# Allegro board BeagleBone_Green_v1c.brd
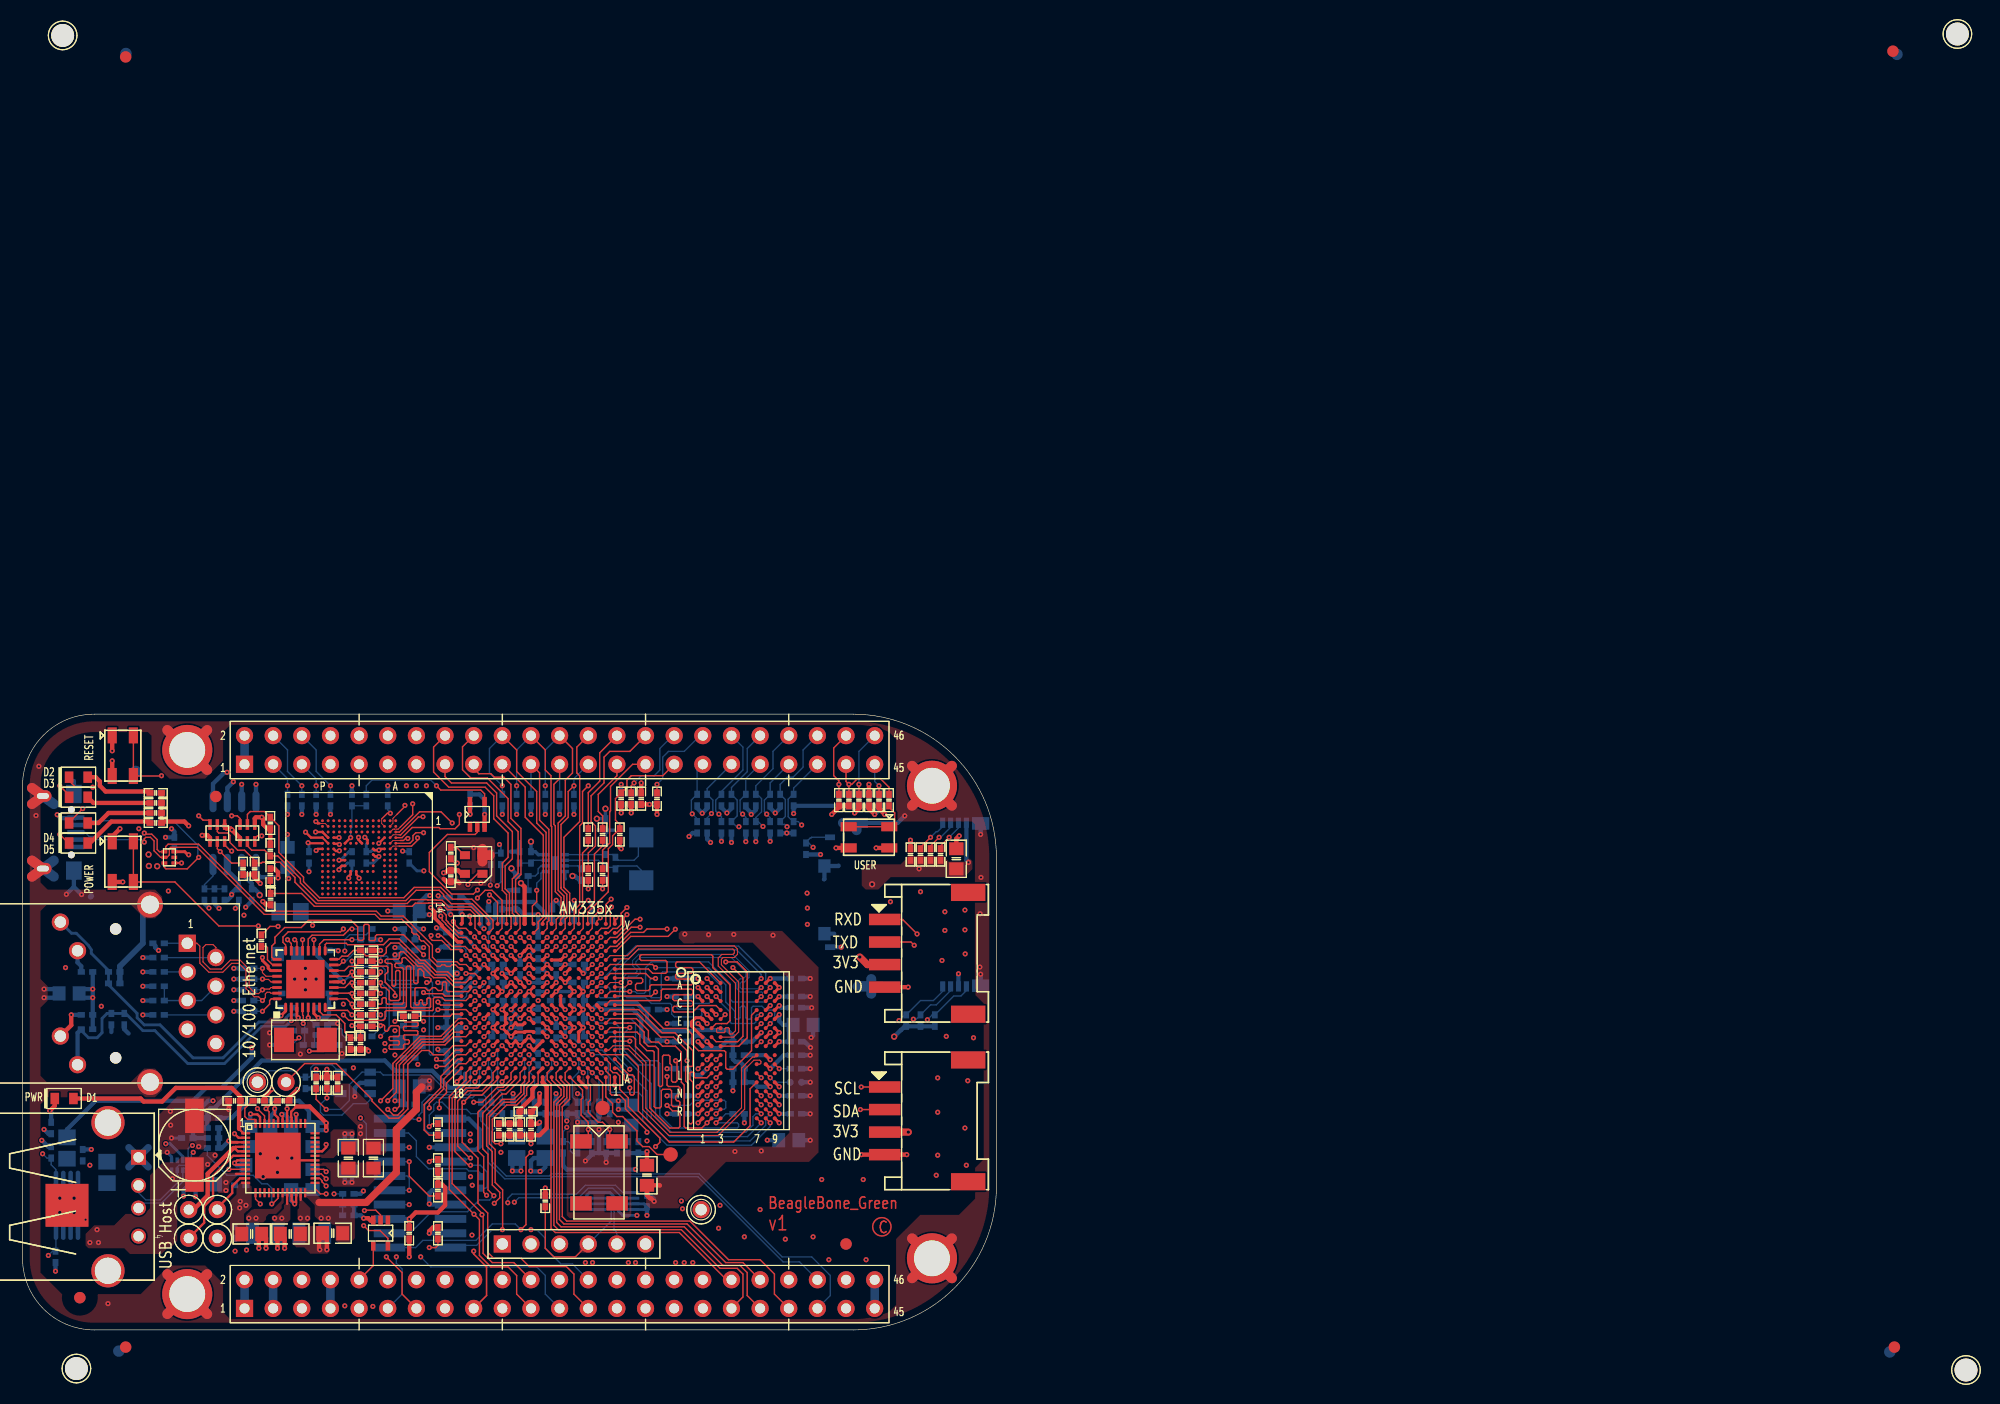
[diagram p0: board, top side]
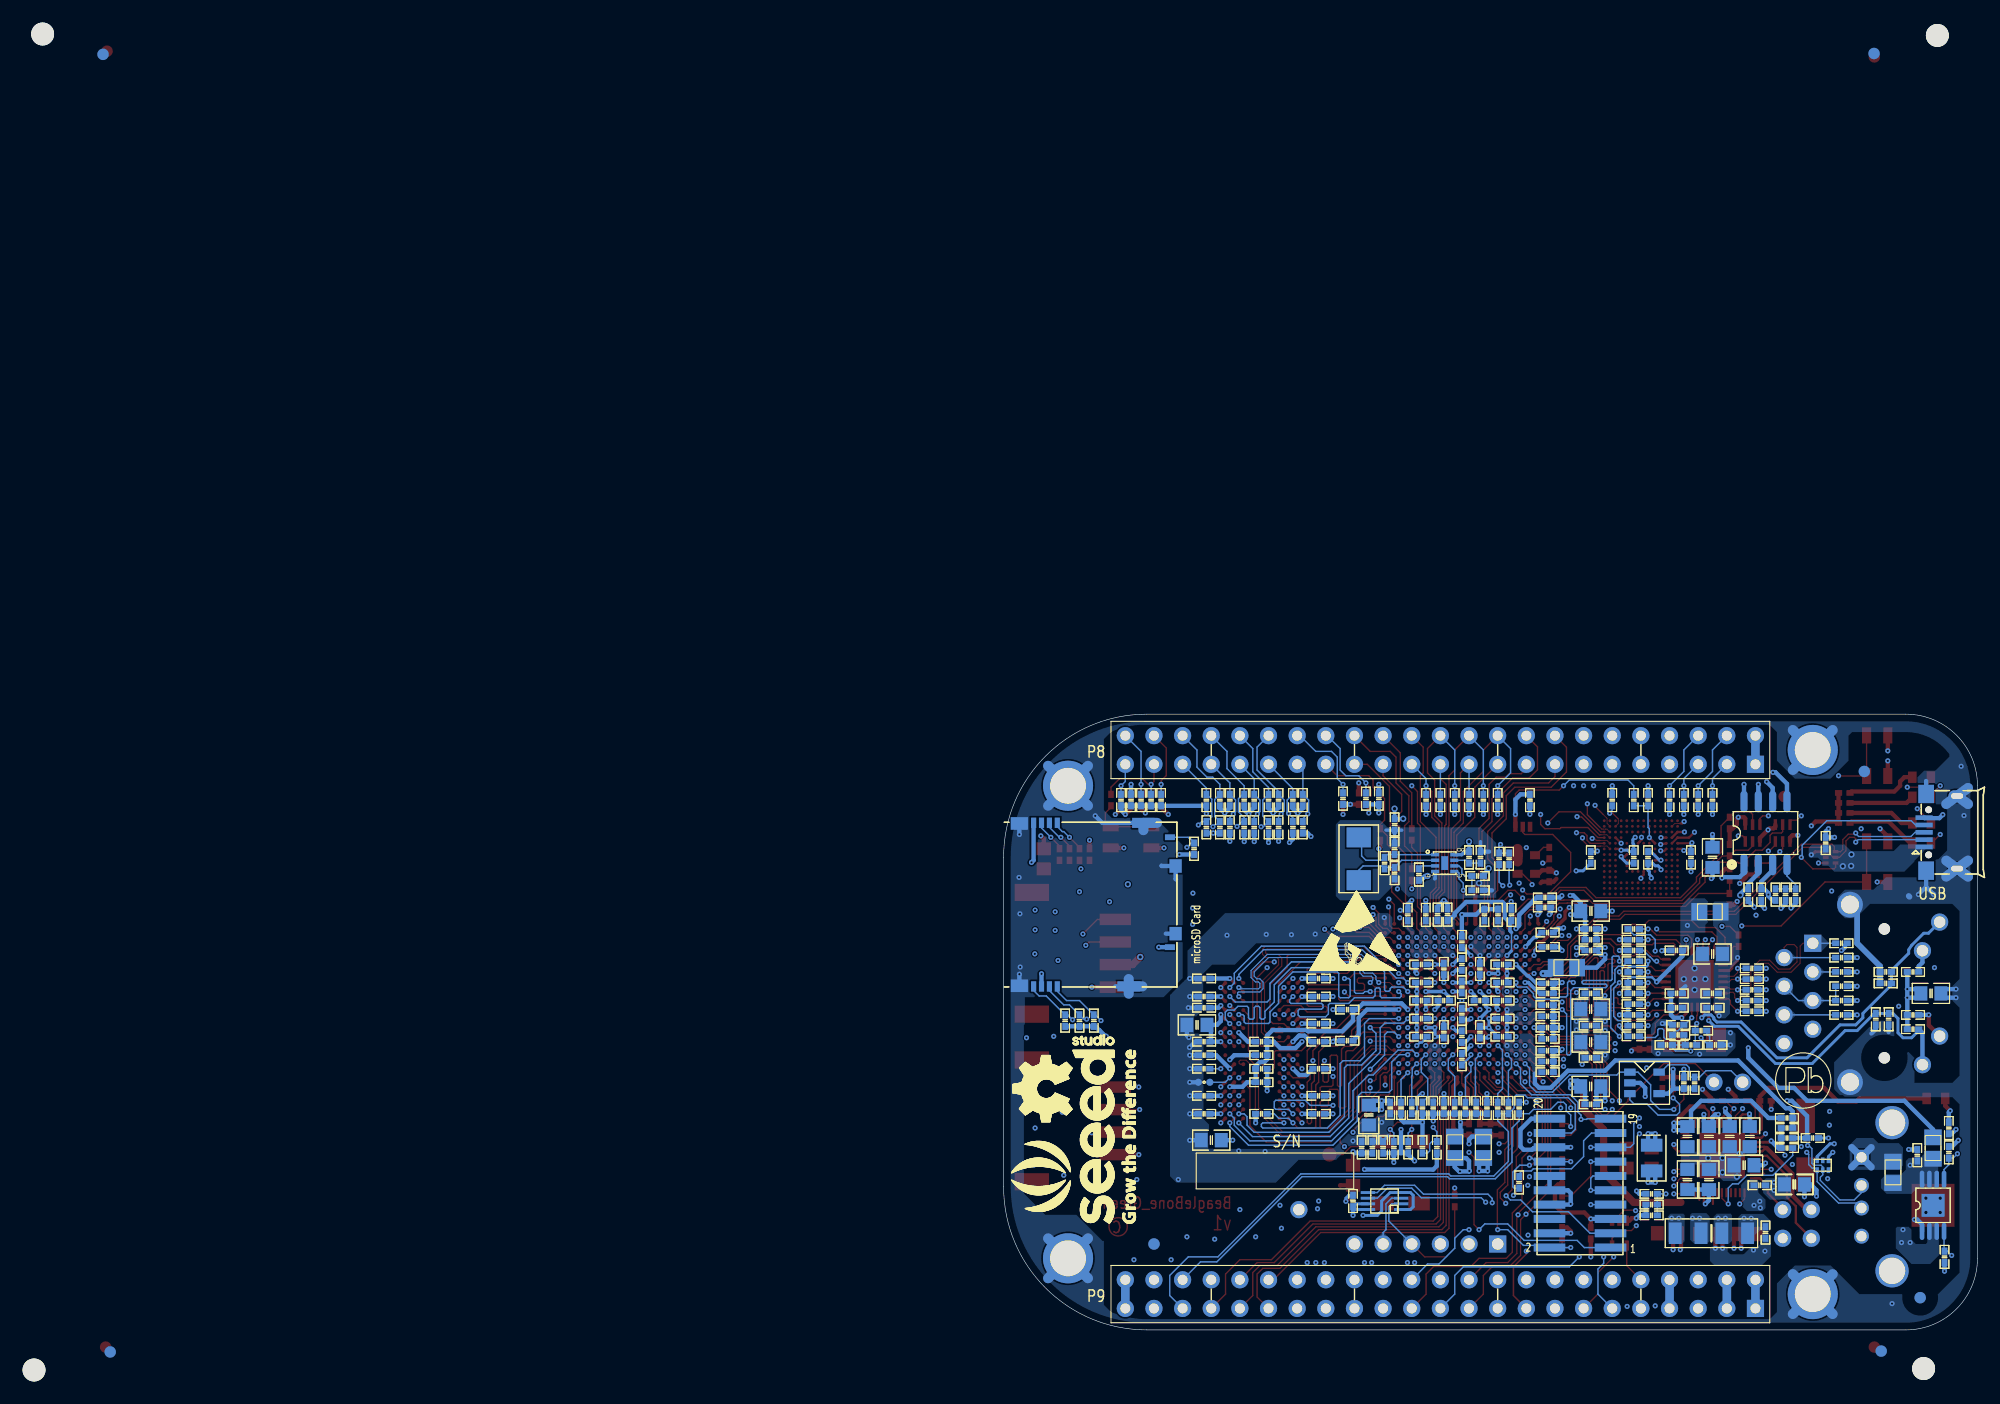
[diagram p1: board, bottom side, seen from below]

Outline 86.36 x 54.61 mm; copper layers: TOP, LYR2_GND, LYR3, LYR4, LYR5_PWR, BOTTOM. Coordinates in mm from the lower left corner of the outline.
Outline path: 0,48.26 0,6.35 arc(1.86,1.86) 6.35,0 73.66,0 arc(82.64,3.72) 86.36,12.7 86.36,41.91 arc(82.64,50.89) 73.66,54.61 6.35,54.61 arc(1.86,52.75) 0,48.26

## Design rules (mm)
constraint set DEFAULT: min track width 0.121
net group RX: nets RXN RXP
net group TX: nets TXN TXP
net group USB0: nets USB0_DM USB0_DP
net group USB1: nets USB1_DM USB1_DP
net group CLK: nets MMC0_CLKO
net group DDR_ADD: nets DDR_A0 DDR_A1 DDR_A2 DDR_A3 DDR_A4 DDR_A5 DDR_A6 DDR_A7 DDR_A8 DDR_A9 DDR_A10 DDR_A11 DDR_A12 DDR_A13 DDR_A14 DDR_BA0 DDR_BA1 DDR_BA2 DDR_CASN DDR_CKE DDR_CLK DDR_CLKN DDR_CSN DDR_ODT DDR_RASN DDR_WEN
net group DDR_DQ0: nets DDR_D0 DDR_D1 DDR_D2 DDR_D3 DDR_D4 DDR_D5 DDR_D6 DDR_D7 DDR_DQM0 DDR_DQS0 DDR_DQSN0
net group DDR_DQ1: nets DDR_D8 DDR_D9 DDR_D10 DDR_D11 DDR_D12 DDR_D13 DDR_D14 DDR_D15 DDR_DQM1 DDR_DQS1 DDR_DQSN1
nets with their own width: min track width 0.203; nets USB1_VBUS

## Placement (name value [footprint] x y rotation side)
C1  10uF,10V  [805]  20.32 8.51 180 top
C2  10uF,10V  [805]  16.23 12.9 0 bottom
C3  0.1uf,6.3V  [402]  20.95 20.32 180 top
C4  10uF,10V  [805]  20.19 17.14 90 bottom
C7  10uF,10V  [805]  23.81 13.34 270 bottom
C8  10uF,10V  [805]  25.72 13.34 270 bottom
C9  10uF,10V  [805]  23.75 8.51 180 top
C10  10uF,10V  [805]  20.7 14.61 180 bottom
C11  10uF,10V  [805]  28.89 15.24 270 top
C12  10uF,10V  [805]  27.5 8.57 0 top
C13  10uF,10V  [805]  23.81 17.14 90 bottom
C14  10uF,10V  [805]  25.72 17.14 90 bottom
C15  10uF,10V  [805]  21.97 17.14 90 bottom
C16  2.2uF,6.3V  [402]  14.61 17.02 180 bottom
C17  2.2uF,6.3V  [402]  20.32 38.61 270 bottom
C18  2.2uF,6.3V  [402]  18.8 20.32 180 top
C19  470pF,6.3V  [402]  17.02 38.61 270 bottom
C20  0.1uf,6.3V  [402]  19.18 38.61 270 bottom
C21  18pF,50V  [402]  50.48 16.19 90 bottom
C22  18pF,50V  [402]  51.75 16.19 90 bottom
C24  2.2uF,6.3V  [402]  28.89 11.11 0 bottom
C25  18pF,50V  [402]  51.69 42.67 90 bottom
C26  18pF,50V  [402]  51.69 40.51 270 bottom
C28  0.1uf,6.3V  [402]  55.88 28.41 0 bottom
C29  0.1uf,6.3V  [402]  34.29 8.57 270 top
C30  0.1uf,6.3V  [402]  28.89 10.16 0 bottom
C31  0.1uf,6.3V  [402]  43.18 17.78 270 top
C32  0.001uf,50V  [402]  42.23 17.78 270 top
C33  0.1uf,6.3V  [402]  44.13 17.78 270 top
C34  100uF,6.3V  [RD205SMD_250D]  15.24 16.38 90 top
C35  0.1uf,6.3V  [402]  5.33 15.49 90 bottom
C36  0.1uf,6.3V  [402]  13.46 43.18 90 bottom
C37  0.1uf,6.3V  [402]  27.94 21.91 270 top
C38  0.1uf,6.3V  [402]  34.29 34.61 180 bottom
C39  10uF,10V  [805]  34.29 25.53 0 bottom
C40  10uF,10V  [805]  34.29 28.45 0 bottom
C41  0.1uf,6.3V  [402]  42.12 32.41 180 bottom
C42  0.1uf,6.3V  [402]  45.72 32.41 270 bottom
C43  0.1uf,6.3V  [402]  47.32 32.01 90 bottom
C44  0.1uf,6.3V  [402]  38.12 25.81 180 bottom
C45  0.1uf,6.3V  [402]  38.1 29.84 180 bottom
C46  0.1uf,6.3V  [402]  44.12 29.21 0 bottom
C47  0.1uf,6.3V  [402]  45.72 30.41 270 bottom
C48  0.1uf,6.3V  [402]  47.32 29.21 0 bottom
C49  0.1uf,6.3V  [402]  45.72 28.01 90 bottom
C50  0.1uf,6.3V  [402]  47.32 26.41 90 bottom
C51  0.1uf,6.3V  [402]  34.29 29.84 180 bottom
C52  0.1uf,6.3V  [402]  34.29 26.99 180 bottom
C53  0.1uf,6.3V  [402]  34.29 24.13 180 bottom
C54  0.1uf,6.3V  [402]  38.12 26.81 180 bottom
C55  10uF,10V  [805]  31.11 15.24 270 top
C56  0.1uf,6.3V  [402]  45.72 34.41 270 bottom
C57  0.1uf,6.3V  [402]  54.86 47.12 270 top
C58  0.1uf,6.3V  [402]  42.52 36.81 90 bottom
C59  0.1uf,6.3V  [402]  43.5 19.68 270 bottom
C60  0.1uf,6.3V  [402]  42.12 27.61 180 bottom
C61  0.1uf,6.3V  [402]  75.06 46.99 270 top
C62  10uF,10V  [805]  34.29 21.59 0 bottom
C63  0.1uf,6.3V  [402]  44.12 26.41 90 bottom
C64  0.1uf,6.3V  [402]  34.29 20 180 bottom
C65  0.1uf,6.3V  [402]  42.12 29.21 180 bottom
C66  0.1uf,6.3V  [402]  42.12 30.81 180 bottom
C67  0.1uf,6.3V  [402]  34.29 35.56 180 bottom
C68  0.1uf,6.3V  [402]  48.92 36.81 270 bottom
C69  0.1uf,6.3V  [402]  38.12 28.81 0 bottom
C70  0.1uf,6.3V  [402]  42.12 26.01 180 bottom
C71  0.1uf,6.3V  [402]  38.35 37.47 180 bottom
C72  0.1uf,6.3V  [402]  45.72 26.01 270 bottom
C73  0.1uf,6.3V  [402]  49.32 32.41 0 bottom
C74  0.1uf,6.3V  [402]  50.52 36.81 270 bottom
C75  0.1uf,6.3V  [402]  53.09 47.12 270 bottom
C76  0.1uf,6.3V  [402]  75.06 46.99 270 bottom
C77  10uF,10V  [805]  34.29 37.15 180 bottom
C78  0.1uf,6.3V  [402]  34.29 33.66 0 bottom
C79  0.1uf,6.3V  [402]  38.12 27.81 180 bottom
C80  0.1uf,6.3V  [402]  41.32 36.81 90 bottom
C81  0.1uf,6.3V  [402]  47.88 36.83 90 bottom
C82  0.1uf,6.3V  [402]  38.12 24.77 180 bottom
C83  0.1uf,6.3V  [402]  38.12 23.81 180 bottom
C84  0.1uf,6.3V  [402]  46.99 36.83 90 bottom
C85  0.1uf,6.3V  [402]  38.12 22.86 180 bottom
C86  0.1uf,6.3V  [402]  38.12 35.24 180 bottom
C87  0.1uf,6.3V  [402]  38.1 30.73 180 bottom
C88  0.1uf,6.3V  [402]  45.72 24.01 270 bottom
C89  1uF,10V  [402]  46.35 19.68 270 bottom
C90  1uF,10V  [402]  44.45 19.68 270 bottom
C91  1uF,10V  [402]  45.4 19.68 270 bottom
C92  0.1uf,6.3V  [402]  48.26 19.68 270 bottom
C93  0.1uf,6.3V  [402]  45.09 17.78 270 top
C94  0.1uf,6.3V  [402]  44.12 32.01 270 bottom
C95  10uF,10V  [805]  53.98 19.05 90 bottom
C96  10uF,10V  [805]  55.37 13.72 90 top
C97  0.1uf,6.3V  [402]  49.32 30.81 180 bottom
C98  0.1uf,6.3V  [402]  49.32 29.21 180 bottom
C99  0.1uf,6.3V  [402]  49.32 27.61 180 bottom
C100  0.1uf,6.3V  [402]  49.32 26.01 180 bottom
C101  0.1uf,6.3V  [402]  52.07 19.68 270 bottom
C102  0.1uf,6.3V  [402]  53.66 16.19 90 bottom
C103  0.1uf,6.3V  [402]  54.61 16.19 90 bottom
C104  1uF,10V  [402]  49.21 19.68 270 bottom
C105  0.1uf,6.3V  [402]  47.31 19.68 270 bottom
C106  1uF,10V  [402]  43.72 36.81 90 bottom
C107  0.1uf,6.3V  [402]  58.42 31.17 180 bottom
C108  0.1uf,6.3V  [402]  58.42 29.57 180 bottom
C109  0.1uf,6.3V  [402]  58.42 27.17 180 bottom
C110  0.1uf,6.3V  [402]  58.42 25.57 180 bottom
C111  0.1uf,6.3V  [402]  58.42 23.16 180 bottom
C112  0.1uf,6.3V  [402]  58.42 20.76 180 bottom
C113  0.1uf,6.3V  [402]  58.42 19.16 180 bottom
C114  0.1uf,6.3V  [402]  68.58 31.17 0 bottom
C115  0.1uf,6.3V  [402]  68.58 29.57 0 bottom
C116  0.1uf,6.3V  [402]  68.58 28.57 0 bottom
C117  0.1uf,6.3V  [402]  68.58 25.57 0 bottom
C118  10uF,10V  [805]  69.22 27.05 180 bottom
C119  0.1uf,6.3V  [402]  68.58 24.36 0 bottom
C120  0.1uf,6.3V  [402]  68.58 20.76 0 bottom
C121  0.1uf,6.3V  [402]  68.58 19.16 0 bottom
C122  10uF,10V  [805]  67.94 16.83 180 bottom
C123  0.001uf,50V  [402]  63.5 24.36 0 bottom
C124  0.1uf,6.3V  [402]  63.5 21.96 180 bottom
C125  2.2uF,6.3V  [402]  32.38 46.99 90 bottom
C126  10uF,10V  [805]  23.5 41.91 90 bottom
C127  0.1uf,6.3V  [402]  25.4 41.91 270 bottom
C128  0.1uf,6.3V  [402]  29.21 41.91 90 bottom
C129  0.1uf,6.3V  [402]  30.48 41.91 270 bottom
C130  0.1uf,6.3V  [402]  34.29 41.91 270 bottom
C131  0.1uf,6.3V  [402]  23.5 28.57 0 bottom
C132  0.1uf,6.3V  [402]  23.5 29.84 0 bottom
C133  10uF,10V  [805]  23.5 33.34 180 bottom
C134  1uF,10V  [402]  26.67 28.57 180 bottom
C135  0.1uf,6.3V  [402]  26.67 33.66 0 bottom
C136  470pF,6.3V  [0402]  26.67 29.84 180 bottom
C137  33pF,4 EMI  [402]  12.06 34.29 180 bottom
C138  33pF,4 EMI  [402]  12.06 33.02 180 bottom
C139  33pF,4 EMI  [402]  12.06 31.75 180 bottom
C140  33pF,4 EMI  [402]  12.06 27.94 180 bottom
C141  0.022uF,10V  [402]  12.06 30.48 180 bottom
C142  30pF,50V  [402]  23.24 25.27 180 bottom
C143  30pF,50V  [402]  27.56 25.27 0 bottom
C152  0.1uf,6.3V  [402]  26.04 21.91 90 bottom
C153  10uF,10V  [805]  82.8 41.78 90 top
C154  0.1uf,6.3V  [402]  78.74 42.16 90 top
C155  0.1uf,6.3V  [402]  55.37 11.43 270 bottom
C158  0.1uf,6.3V  [402]  39.69 46.99 90 bottom
C159  0.1uf,6.3V  [402]  37.97 40.26 270 top
C161  33pF,4 EMI  [402]  26.54 27.05 0 bottom
C162  33pF,4 EMI  [402]  29.08 25.4 90 top
C163  100pF,4 EMI  [402]  8.13 31.75 0 bottom
C164  100pF,4 EMI  [402]  9.02 27.56 270 bottom
C165  100nF,4 EMI  [402]  8.13 30.73 0 bottom
C166  100nF,4 EMI  [402]  7.87 27.56 270 bottom
D1  LTST-C191TBKT  [LED_0603]  3.68 20.52 0 top
D2  LTST-C191TBKT  [LED_0603]  4.95 49.02 0 top
D3  LTST-C191TBKT  [LED_0603]  4.95 47.24 0 top
D4  LTST-C191TBKT  [LED_0603]  4.95 44.96 0 top
D5  LTST-C191TBKT  [LED_0603]  4.95 43.18 0 top
FB1  150OHM800mA  [SM-7351-IND-0805]  36.45 32.13 0 bottom
FB2  150OHM800mA  [SM-7351-IND-0805]  46.35 16.19 270 bottom
FB3  150OHM800mA  [SM-7351-IND-0805]  43.81 16.19 270 bottom
FB4  150OHM800mA  [SM-7351-IND-0805]  23.72 37.08 180 bottom
FB7  150OHM800mA  [SM-7351-IND-0805]  7.49 13.97 90 bottom
FB8  0.1R,0805  [SM-7351-IND-0805]  3.94 16.13 270 bottom
J1  HEADER 6  [SIP6]  42.55 7.62 90 top
J4  GroveHDR  [4P-SMD-2_0-90D]  76.45 18.54 270 top
J5  GroveHDR  [4P-SMD-2_0-90D]  76.45 33.4 270 top
L1  LQM2HPN2R2MG0L  [2520]  21.53 8.57 180 bottom
L2  LQM2HPN2R2MG0L  [2520]  25.65 8.57 0 bottom
L3  LQM2HPN2R2MG0L  [2520]  28.89 15.24 270 bottom
MTG1  MHOLE  [MTGH200C125D_PL]  14.61 3.17 90 top
MTG2  MHOLE  [MTGH200C125D_PL]  80.64 6.35 90 top
MTG3  MHOLE  [MTGH200C125D_PL]  14.61 51.44 90 top
MTG4  MHOLE  [MTGH200C125D_PL]  80.64 48.26 90 top
NOREF  -  []  86.36 27.94 0 top
NOREF#2  -  []  85.72 28.57 0 top
NOREF#3  -  [unnamed#2]  5.08 2.86 270 top
NOREF#4  -  []  6.35 54.61 0 top
NOREF#5  -  []  81.92 52.07 0 top
NOREF#6  -  []  80.64 6.35 0 top
NOREF#7  -  []  86.36 12.7 0 top
NOREF#8  -  []  0 0 0 top
NOREF#9  -  [unnamed#2]  17.14 47.31 270 top
NOREF#10  -  []  85.72 28.57 0 top
NOREF#11  -  []  -368.3 -256.54 0 top
NOREF#12  -  []  14.61 3.17 0 top
NOREF#13  -  [unnamed#3]  172.34 -3.56 0 top
NOREF#14  -  []  86.36 39.69 0 top
NOREF#15  -  [unnamed#2]  73.03 7.62 270 top
NOREF#16  -  [unnamed#3]  171.58 114.94 180 top
NOREF#17  -  []  80.64 48.26 0 top
NOREF#18  -  []  0 0 0 top
NOREF#19  -  []  85.72 39.05 0 top
NOREF#20  -  [unnamed#3]  3.56 114.81 180 top
NOREF#21  -  []  14.61 51.44 0 top
NOREF#22  -  [unnamed#2]  165.99 -1.52 270 top
NOREF#23  -  [unnamed#2]  9.14 112.9 270 top
NOREF#24  -  []  -368.17 -256.47 0 top
NOREF#25  -  [unnamed#3]  4.78 -3.43 0 top
NOREF#26  -  []  14.61 3.17 0 top
NOREF#27  -  [unnamed#2]  9.14 -1.52 270 top
NOREF#28  -  []  80.64 6.35 0 top
NOREF#29  -  [unnamed#2]  165.86 113.41 270 top
NOREF#30  -  []  -11.96 0 90 top
NOREF#31  -  []  0 -11.96 0 top
NOREF#32  -  [unnamed#2]  5.08 2.86 270 bottom
NOREF#33  -  [unnamed#2]  8.53 -1.88 270 bottom
NOREF#34  -  []  83.82 13.97 90 bottom
NOREF#35  -  [unnamed#2]  165.58 -1.96 270 bottom
NOREF#36  -  [unnamed#2]  166.22 113.13 90 bottom
NOREF#37  -  [unnamed#2]  10.03 49.53 270 bottom
NOREF#38  -  []  1.91 53.34 180 bottom
NOREF#39  -  [unnamed#2]  73.03 7.62 270 bottom
NOREF#40  -  [unnamed#2]  9.17 113.21 90 bottom
P2  CTI JTAG,DNI  [HEADER10X2_SMD]  35.24 13.02 90 bottom
P3  DIP USB A TYPE FMAL  [USB-003A-4P-90D]  7.57 11.81 270 top
P4  SMD Micro USB-B-without POST-W/P  [5P-USB-B]  4.98 44.13 90 bottom
P5  LPJ0011BBNL  [RJ45-7499010211A]  14.61 34.29 270 top
P8  FEMALE HEADER 2x23  [HEADER23X2]  19.68 50.16 0 top
P9  FEMALE HEADER 2x23  [HEADER23X2]  19.68 1.91 0 top
P10  SCHA5B0200  [SD-MICRO-SCHA5B0300]  81.6 37.72 270 bottom
Q1  DMC56404  [SMINI6-F3-B]  19.94 44.07 180 top
Q2  DMC56404  [SMINI6-F3-B]  17.27 44.07 180 top
R1  100K,1%  [402]  23.11 20.32 180 top
R3  1.5K,1%  [402]  26.04 21.91 270 top
R4  1.5K,1%  [402]  26.99 21.91 270 top
R5  0,1%  [402]  16.89 17.02 180 bottom
R6  0,1%  [402]  18.8 8.64 270 bottom
R7  0,1%  [402]  16.89 16.13 180 bottom
R8  0,1%  [402]  16.89 17.91 180 bottom
R9  0,1%,DNI  [402]  16.89 18.8 0 bottom
R10  470K,1%  [402]  16.13 38.61 270 bottom
R11  280K,1%  [402]  17.91 38.61 90 bottom
R12  4.75K,5%  [402]  2.54 17.91 90 bottom
R14  10K,1%  [402]  28.89 12.06 180 bottom
R17  1M,1%  [402]  52.58 41.4 270 bottom
R18  33  [0402]  40.64 13.08 90 bottom
R19  0,1%  [402]  41.59 19.68 270 bottom
R20  0,1%  [402]  42.55 19.68 90 bottom
R22  49.9,1%  [402]  55.88 25.65 180 bottom
R23  4.75K,1%  [402]  36.83 12.38 270 top
R24  4.75K,1%  [402]  36.83 14.61 90 top
R25  4.75K,1%  [402]  36.83 8.57 90 top
R26  4.75K,1%  [402]  50.16 19.68 90 bottom
R27  0,1%  [402]  44.61 19.37 180 top
R28  33  [0402]  34.29 27.81 180 top
R29  0,1%  [402]  51.69 44.83 270 bottom
R30  0,1%  [402]  52.7 16.19 270 bottom
R45  22  [0402]  50.16 43.94 90 top
R46  0  [0402]  51.44 43.94 90 top
R47  0  [0402]  51.44 40.39 90 top
R48  0  [0402]  50.16 40.39 90 top
R49  0,1%  [402]  38.1 33.97 0 bottom
R50  0,1%  [402]  36.83 17.78 270 top
R51  0,1%  [402]  40.64 19.68 90 bottom
R52  10K,1%  [402]  2.54 15.75 270 bottom
R53  10K,1%  [402]  2.92 6.48 270 bottom
R54  10K,1%  [402]  51.12 19.68 90 bottom
R55  100K,1%,DNI  [402]  54.23 47.12 90 bottom
R56  100K,1%  [402]  53.09 47.12 90 top
R57  100K,1%,DNI  [402]  59.82 46.99 90 bottom
R58  100K,1%,DNI  [402]  60.71 46.99 90 bottom
R59  100K,1%,DNI  [402]  56.26 47.12 90 bottom
R60  100K,1%,DNI  [402]  61.98 46.99 90 bottom
R61  100K,1%,DNI  [402]  62.87 46.99 90 bottom
R62  100K,1%,DNI  [402]  64.14 46.99 90 bottom
R63  100K,1%,DNI  [402]  65.02 46.99 90 bottom
R64  100K,1%,DNI  [402]  66.29 46.99 90 bottom
R65  100K,1%  [402]  67.18 46.99 90 bottom
R66  100K,1%  [402]  68.38 46.99 90 bottom
R67  100K,1%  [402]  72.39 46.99 90 bottom
R68  100K,1%  [402]  73.28 46.99 90 bottom
R69  100K,1%,DNI  [402]  74.17 46.99 90 bottom
R70  100K,1%,DNI  [402]  75.95 46.99 90 bottom
R71  4.75K,5%  [402]  11.81 44.96 180 top
R72  4.75K,5%  [402]  11.81 47.62 180 top
R73  4.75K,5%  [402]  11.81 46.74 180 top
R74  4.75K,5%  [402]  11.81 45.85 180 top
R75  100,1%  [402]  76.83 46.99 270 top
R76  100K,1%  [402]  21.97 42.55 90 top
R77  100K,1%  [402]  21.97 44.96 270 top
R78  100K,1%  [402]  19.56 40.89 270 top
R79  100K,1%  [402]  20.57 40.89 270 top
R80  100K,1%  [402]  53.98 47.12 270 top
R81  100K,1%,DNI  [402]  52.96 43.94 270 top
R82  100K,1%  [402]  59.82 44.58 270 bottom
R83  100K,1%  [402]  60.71 44.58 270 bottom
R84  100K,1%  [402]  56.26 47.12 270 top
R85  100K,1%  [402]  61.98 44.58 270 bottom
R86  100K,1%  [402]  62.87 44.58 270 bottom
R87  100K,1%  [402]  64.14 44.58 270 bottom
R88  100K,1%  [402]  65.02 44.58 270 bottom
R89  100K,1%  [402]  66.29 44.58 270 bottom
R90  100K,1%,DNI  [402]  67.18 44.58 270 bottom
R91  100K,1%,DNI  [402]  68.38 44.58 270 bottom
R92  100K,1%,DNI  [402]  72.39 46.99 270 top
R93  100K,1%,DNI  [402]  73.28 46.99 270 top
R94  100K,1%  [402]  74.17 46.99 270 top
R95  100K,1%  [402]  75.95 46.99 270 top
R96  10K,1%  [402]  68.58 23.16 180 bottom
R97  1.5K,1%  [402]  63.5 19.16 180 bottom
R98  10K,1%  [402]  63.5 25.57 180 bottom
R99  240  [SM-7351-RES-0402]  68.58 21.96 180 bottom
R100  10K,1%  [402]  63.5 23.16 180 bottom
R101  10K,1%  [402]  48.9 46.99 90 bottom
R102  10K,1%  [402]  46.35 46.99 90 bottom
R103  10K,1%  [402]  26.04 46.99 90 bottom
R104  10K,1%  [402]  27.3 46.99 90 bottom
R105  10K,1%  [402]  47.62 46.99 90 bottom
R106  10K,1%  [402]  43.81 46.99 90 bottom
R107  10K,1%  [402]  23.5 46.99 90 bottom
R108  10K,1%  [402]  24.77 46.99 90 bottom
R109  10K,1%  [402]  42.55 46.99 90 bottom
R110  10K,1%  [402]  45.09 46.99 90 bottom
R111  10K,1%  [402]  29.21 46.99 270 bottom
R112  1.5K,1%  [402]  30.48 30.8 0 bottom
R113  1.5K,1%  [402]  30.48 33.66 0 bottom
R114  1.5K,1%  [402]  30.48 29.84 0 bottom
R115  10K,1%  [402]  30.48 31.75 0 bottom
R116  10K,1%  [402]  30.48 27.94 0 bottom
R117  10K,1%  [402]  30.48 28.89 0 bottom
R118  10K,1%  [402]  29.97 25.4 270 top
R119  1.5K,1%  [402]  30.48 33.66 180 top
R120  49.9,1%  [402]  20 29.21 180 bottom
R121  49.9,1%  [402]  20 30.16 180 bottom
R122  49.9,1%  [402]  20 31.11 180 bottom
R123  49.9,1%  [402]  20 32.07 180 bottom
R124  10,1%,DNI  [402]  30.48 26.92 180 top
R125  100,1%  [402]  30.48 27.94 180 top
R126  100,1%  [402]  30.48 28.89 180 top
R127  100,1%  [402]  30.48 29.84 180 top
R128  100,1%  [402]  30.48 30.8 180 top
R129  100,1%  [402]  21.18 34.52 270 top
R130  470,5%  [402]  5.71 27.94 180 bottom
R131  100,1%  [402]  30.48 26.99 180 bottom
R132  470,5%  [402]  5.71 31.75 180 bottom
R133  100,1%  [402]  30.48 31.75 180 top
R134  100,1%  [402]  30.48 35.56 180 bottom
R135  10K,1%  [402]  5.71 26.67 0 bottom
R136  0.1R,0805  [805]  4.13 29.84 180 bottom
R137  0,1%  [402]  12.06 29.21 180 bottom
R138  100,1%  [402]  30.48 32.7 180 bottom
R139  100,1%  [402]  30.48 32.7 180 top
R140  0,1%,DNI  [402]  30.48 26.04 180 bottom
R141  1M,1%,DNI  [402]  25.4 25.27 0 bottom
R142  0,1%  [402]  26.54 26.16 0 bottom
R143  10,1%  [402]  24.51 26.54 180 bottom
R144  12.1K,1%  [402]  20 28.26 180 bottom
R145  10K,1%  [402]  30.48 34.61 0 bottom
R150  10K,1%  [402]  79.63 42.16 90 top
R151  10K,1%  [402]  81.41 42.16 90 top
R152  10K,1%  [402]  80.9 27.43 90 bottom
R153  10K,1%  [402]  79.63 27.43 90 bottom
R154  10K,1%  [402]  78.36 27.43 90 bottom
R155  10K,1%  [402]  80.52 42.16 90 top
R156  10K,1%  [402]  25.08 21.91 90 bottom
R157  10K,1%  [402]  69.47 42.67 270 bottom
R159  0,1%  [402]  38.35 38.35 0 bottom
R160  0,1%  [402]  42.42 41.78 90 bottom
R161  0,1%  [402]  41.53 41.78 90 bottom
R162  0,1%  [402]  30.48 46.99 270 bottom
R163  4.75K,1%  [402]  47.94 16.19 90 bottom
R164  4.75K,1%  [402]  49.21 16.19 90 bottom
R165  100K,1%  [402]  46.35 11.43 90 top
R167  33  [0402]  37.97 42.29 270 top
R168  0R,1%  [402]  19.3 12.83 180 bottom
R169  0,1% DNP  [402]  21.97 40.39 90 top
R170  0,1% DNP  [402]  22 38.2 270 top
R171  4.75K,5%  [402]  49.53 40.39 90 bottom
R172  4.75K,5%  [402]  44.32 40.26 0 bottom
R173  4.75K,5%  [402]  44.07 41.91 90 bottom
R174  4.75K,5%,DNP  [402]  44.32 38.99 180 bottom
R175  4.75K,5%.DNP  [402]  45.09 41.91 270 bottom
S1  SMD Button Top  [SW_4P]  8.89 50.93 270 top
S2  SMD Button Top  [SW_4P]  75.06 43.69 180 top
S3  SMD Button Top  [SW_4P]  8.89 41.53 270 top
TP1  TESTPT1  [TP1-8040]  60.17 10.67 0 top
TP2  TESTPT1  [TP60C_SMD]  57.47 15.56 0 top
TP3  TESTPT1  [TP60C_SMD]  51.44 19.68 0 top
TP4  TESTPT1  [TP1-8040]  20.83 21.97 0 top
TP5  TESTPT1  [TP60C33D]  14.73 10.67 0 top
TP6  TESTPT1  [TP60C33D]  14.73 8.13 0 top
TP7  TESTPT1  [TP60C33D]  17.27 10.67 0 top
TP8  TESTPT1  [TP60C33D]  17.27 8.13 0 top
TP9  TESTPT1  [TP60C33D]  23.37 21.97 0 top
U2  TPS65217C  [U_48_RSL]  22.86 15.24 0 top
U3  SN74LVC1G06DCK  [DCK5_2P15X1P4]  40.32 45.72 0 top
U4  TL5209  [SO8-25X75]  18.8 44.07 180 bottom
U5  AM3358BZCZ100  [AM33XX_15X15]  45.72 29.21 180 top
U7  24LC32A  [SOT23-5]  29.53 21.91 270 bottom
U8  TPS2051 (DGN)  [DGN-16X60]  3.94 11.05 180 bottom
U9  TPD4S012  [U_6_DRY]  13.72 14.61 180 bottom
U10  TPD4S012  [U_6_DRY]  13.02 41.91 270 top
U12  MT41K256M16HA -125:E  [BGA96_T9_P8_9X14]  63.5 24.77 0 top
U13  MEM_MNAND_4GB  [BGA153_P14_P5_11P5X13]  29.84 41.91 270 top
U14  LAN8710A  [QFN32_5X5MM_EP3P3MM]  25.08 31.11 0 top
U15  SN74LVC2G241  [U_8_DCU]  52.58 11.43 90 bottom
U16  SN74LVC1G07DCK  [DCK5_2P15X1P4]  31.75 8.59 180 top
U17  SSDCI3128AF  [TDFN8_P5_2P0]  47.24 41.4 270 bottom
Y1  32.768KHz MC-306  [XTAL4_126-216SMD]  51.12 13.97 270 top
Y2  24MHz  [XTAL150SMD_125X196]  54.86 41.78 90 bottom
Y3  25.000MHz  [XTAL150SMD_125X196]  25.08 25.72 180 top
Y4  24.576MHZ  [OSC4_61X65LS_79X98SMD]  40.01 41.27 90 top

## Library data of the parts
C1 C2 C4 C7-C15 C39 C40 C55 C62 C77 C95 C96 C118 C122 C126 C133 C153 = CAP_10uF_Y5V_10V_10%_0805
C3 C20 C28-C31 C33 C35-C38 C41-C54 C56-C61 C63-C76 C78-C88 C92-C94 C97-C103 C105 C107-C117 C119-C121 C124 C127-C132 C135 C152 C154 C155 C158 C159 = CAP_0.1uF_X5R_6.3V_20% 0201
C16-C18 C125 = CAP_2.2uF_X5R_6.3V_10%_0402
C19 = CAP_470PF_X7R_25V_10%_0402
C21 C22 C25 C26 = CAP_18PF_COG_50V_5%_0402
C24 C89-C91 C104 C106 C134 = CAP_1.0UF_X5R_10V_10%_0402
C32 C123 = CAP_0.001_X7R_50V_5%_0402
C34 = CAP_100UF_TANT_6.3V_3528-21
C136 = 470pF/5%/50V/C0G/0603_0
C137-C140 C161-C166 = CAP_0402_100pF_COG_50V
C141 = CAP_0402_0.1uf_X5R_10V
C142 C143 = CAP_30PF_COG_50V_5%_0402
D1-D5 = LED_LTST-C150GKT_0
FB1-FB4 FB7 FB8 = FER_180_200_0
J1 = HEADER 6: User Part Number: ***
J4 J5 = HEADER 4
L1-L3 = IND_2.2uH_2.6A_10%_SMD
MTG1-MTG4 = MHOLE
P2 = HDR_10x2_CJTAG_0
P3 = CONN_54819-0578_2
P4 = MINI-USB-AB-SOCKET
P5 = CONN_RJ45_MAG_WE_0
P8 P9 = HDR_46_F_2_0.1_0.1
P10 = microSD_CONN_8: User Part Number: X; Tolerance: X
Q1 Q2 = RN1907
R1 R55-R70 R75-R95 R165 = RES_100K_1/16W_1%_0402
R3 R4 R119 R168 = RES_1.5K_1/16W_5%_0402
R5-R9 R23-R26 R50 R51 R112-R118 R159-R164 R169 R170 = RES_4.75K_1/16W_1%_0402
R10 R12 R71-R74 R130 R132 R171-R175 = RES_470_1/10W_5%_0402
R11 = RES_470_1/10W_5%_0402: signal model: 33OHMRESISTOR1_16W5_0402_SM_735_33
R14 = RES_10K_1/16W_1%_0402: signal model: 33OHMRESISTOR1_16W5_0402_SM_735_33
R17 = RES_1M_1/16W_1%_0402: signal model: 33OHMRESISTOR1_16W5_0402_SM_735_33
R18 R47 = RES_33_0402: signal model: 33OHMRESISTOR1_16W5_0402_SM_735_33
R19 R27 R29 R30 R140 R142 R156 = RES_0_1/16W_1%_0402
R20 = RES_0_1/16W_1%_0402: signal model: 33OHMRESISTOR1_16W5_0402_SM_735_33
R22 R120-R123 = RES_4.7K_0402
R28 R45 R46 R48 R167 = RES_33_0402
R49 = RES_100K_1/16W_1%_0402: signal model: 33OHMRESISTOR1_16W5_0402_SM_735_33
R52-R54 R96-R98 R100-R111 R135 R137 R143 R145 R150-R155 R157 = RES_10K_1/16W_1%_0402
R99 = Res
R124-R126 R129 R134 R138 = 100-1/10W-1%-0603_4
R127 R128 R131 R133 R139 = RES_100_1/10W_5%_0402
R136 = RES_0.1_0805
R141 = RES_1M_1/16W_1%_0402
R144 = RES_12.1K_1/16W_1%_0402
S1 S3 = SW_KT11P2JM_2
S2 = SW_KT11P2JM_1
TP1-TP9 = TESTPT1
U2 = PWR_TPS65217_2
U3 = IC_SN74LVC1G06DCK_0
U4 = PWR_TLV70233DBV_0: Tolerance: X; User Part Number: X
U5 = IC_AM335X_ZCZ
U7 = MEM_24LC32_SOT23-5
U8 = TPS2061_1: User Part Number: X; Tolerance: X
U9 U10 = PROT_TPD4S012
U12 = MT47H256M8_7
U13 = MEM_MNAND_2GB
U14 = LAN8710 QFN32_1
U15 = IC_SN74LVC2G241_1
U16 = IC_SN74LVC1G07DCK
U17 = SSDCI3128AF
Y1 = CRYS_32_768KHz_SMD32_1
Y2 = CRYS_24MHz_SCC_0
Y3 = Suntsu ITEMP 25MHz _0.005% 20pf
Y4 = OSC_12MHz_1.3V: Tolerance: TOL*; User Part Number: P/N*

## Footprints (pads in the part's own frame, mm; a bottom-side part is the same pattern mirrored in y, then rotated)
4P-SMD-2_0-90D
  rect 1.524x3.048 smd: (-5.4,7.4) (5.4,7.4)
  rect 1.016x2.794 smd: 1(-3,0) 2(-1,0) 3(1,0) 4(3,0)
5P-USB-B
  round 0.61 hole 0.61 unplated: (-2,-0.65) (2,-0.65)
  rect 0.406x1.524 smd: 1(-1.3,-0.25) 2(-0.65,-0.25) 3(0,-0.25) 4(0.65,-0.25) 5(1.3,-0.25)
  rect 1.626x1.397 smd: 6(3.4,-0.427) 7(-3.4,-0.427)
  oval 1.016x1.524 hole 0.508x1.067: 8(-3.22,-3.175) 9(3.22,-3.175)
402
  rect 0.635x0.508 smd: 1(-0.508,0) 2(0.508,0)
0402
  rect 0.635x0.508 smd: 1(-0.508,0) 2(0.508,0)
805
  rect 1.143x1.27 smd: 1(-0.889,0) 2(0.889,0)
2520
  rect 1.143x1.905 smd: 1(-1.143,0) 2(1.143,0)
AM33XX_15X15
  round 0.356 smd: A1(-6.8,6.8) A2(-6,6.8) A3(-5.2,6.8) A4(-4.4,6.8) A5(-3.6,6.8) A6(-2.8,6.8) A7(-2,6.8) A8(-1.2,6.8) A9(-0.4,6.8) A10(0.4,6.8) A11(1.2,6.8) A12(2,6.8) A13(2.8,6.8) A14(3.6,6.8) A15(4.4,6.8) A16(5.2,6.8) A17(6,6.8) A18(6.8,6.8) B1(-6.8,6) B2(-6,6) B3(-5.2,6) B4(-4.4,6) B5(-3.6,6) B6(-2.8,6) B7(-2,6) B8(-1.2,6) B9(-0.4,6) B10(0.4,6) B11(1.2,6) B12(2,6) B13(2.8,6) B14(3.6,6) B15(4.4,6) B16(5.2,6) B17(6,6) B18(6.8,6) C1(-6.8,5.2) C2(-6,5.2) C3(-5.2,5.2) C4(-4.4,5.2) C5(-3.6,5.2) C6(-2.8,5.2) C7(-2,5.2) C8(-1.2,5.2) C9(-0.4,5.2) C10(0.4,5.2) C11(1.2,5.2) C12(2,5.2) C13(2.8,5.2) C14(3.6,5.2) C15(4.4,5.2) C16(5.2,5.2) C17(6,5.2) C18(6.8,5.2) D1(-6.8,4.4) D2(-6,4.4) D3(-5.2,4.4) D4(-4.4,4.4) D5(-3.6,4.4) D6(-2.8,4.4) D7(-2,4.4) D8(-1.2,4.4) D9(-0.4,4.4) D10(0.4,4.4) D11(1.2,4.4) D12(2,4.4) D13(2.8,4.4) D14(3.6,4.4) D15(4.4,4.4) D16(5.2,4.4) D17(6,4.4) D18(6.8,4.4) E1(-6.8,3.6) E2(-6,3.6) E3(-5.2,3.6) E4(-4.4,3.6) E5(-3.6,3.6) E6(-2.8,3.6) E7(-2,3.6) E8(-1.2,3.6) E9(-0.4,3.6) E10(0.4,3.6) E11(1.2,3.6) E12(2,3.6) E13(2.8,3.6) E14(3.6,3.6) E15(4.4,3.6) E16(5.2,3.6) E17(6,3.6) E18(6.8,3.6) F1(-6.8,2.8) F2(-6,2.8) F3(-5.2,2.8) F4(-4.4,2.8) F5(-3.6,2.8) F6(-2.8,2.8) F7(-2,2.8) F8(-1.2,2.8) F9(-0.4,2.8) F10(0.4,2.8) F11(1.2,2.8) F12(2,2.8) F13(2.8,2.8) F14(3.6,2.8) F15(4.4,2.8) F16(5.2,2.8) F17(6,2.8) F18(6.8,2.8) G1(-6.8,2) G2(-6,2) G3(-5.2,2) G4(-4.4,2) G5(-3.6,2) G6(-2.8,2) G7(-2,2) G8(-1.2,2) G9(-0.4,2) G10(0.4,2) G11(1.2,2) G12(2,2) G13(2.8,2) G14(3.6,2) G15(4.4,2) G16(5.2,2) G17(6,2) G18(6.8,2) H1(-6.8,1.2) H2(-6,1.2) H3(-5.2,1.2) H4(-4.4,1.2) H5(-3.6,1.2) H6(-2.8,1.2) H7(-2,1.2) H8(-1.2,1.2) H9(-0.4,1.2) H10(0.4,1.2) H11(1.2,1.2) H12(2,1.2) H13(2.8,1.2) H14(3.6,1.2) H15(4.4,1.2) H16(5.2,1.2) H17(6,1.2) H18(6.8,1.2) J1(-6.8,0.4) J2(-6,0.4) J3(-5.2,0.4) J4(-4.4,0.4) J5(-3.6,0.4) J6(-2.8,0.4) J7(-2,0.4) J8(-1.2,0.4) J9(-0.4,0.4) J10(0.4,0.4) J11(1.2,0.4) J12(2,0.4) J13(2.8,0.4) J14(3.6,0.4) J15(4.4,0.4) J16(5.2,0.4) J17(6,0.4) J18(6.8,0.4) K1(-6.8,-0.4) K2(-6,-0.4) K3(-5.2,-0.4) K4(-4.4,-0.4) K5(-3.6,-0.4) K6(-2.8,-0.4) K7(-2,-0.4) K8(-1.2,-0.4) K9(-0.4,-0.4) K10(0.4,-0.4) K11(1.2,-0.4) K12(2,-0.4) K13(2.8,-0.4) K14(3.6,-0.4) K15(4.4,-0.4) K16(5.2,-0.4) K17(6,-0.4) K18(6.8,-0.4) L1(-6.8,-1.2) L2(-6,-1.2) L3(-5.2,-1.2) L4(-4.4,-1.2) L5(-3.6,-1.2) L6(-2.8,-1.2) L7(-2,-1.2) L8(-1.2,-1.2) L9(-0.4,-1.2) L10(0.4,-1.2) L11(1.2,-1.2) L12(2,-1.2) L13(2.8,-1.2) L14(3.6,-1.2) L15(4.4,-1.2) L16(5.2,-1.2) L17(6,-1.2) L18(6.8,-1.2) M1(-6.8,-2) M2(-6,-2) M3(-5.2,-2) M4(-4.4,-2) M5(-3.6,-2) M6(-2.8,-2) M7(-2,-2) M8(-1.2,-2) M9(-0.4,-2) M10(0.4,-2) M11(1.2,-2) M12(2,-2) M13(2.8,-2) M14(3.6,-2) M15(4.4,-2) M16(5.2,-2) M17(6,-2) M18(6.8,-2) N1(-6.8,-2.8) N2(-6,-2.8) N3(-5.2,-2.8) N4(-4.4,-2.8) N5(-3.6,-2.8) N6(-2.8,-2.8) N7(-2,-2.8) N8(-1.2,-2.8) N9(-0.4,-2.8) N10(0.4,-2.8) N11(1.2,-2.8) N12(2,-2.8) N13(2.8,-2.8) N14(3.6,-2.8) N15(4.4,-2.8) N16(5.2,-2.8) N17(6,-2.8) N18(6.8,-2.8) P1(-6.8,-3.6) P2(-6,-3.6) P3(-5.2,-3.6) P4(-4.4,-3.6) P5(-3.6,-3.6) P6(-2.8,-3.6) P7(-2,-3.6) P8(-1.2,-3.6) P9(-0.4,-3.6) P10(0.4,-3.6) P11(1.2,-3.6) P12(2,-3.6) P13(2.8,-3.6) P14(3.6,-3.6) P15(4.4,-3.6) P16(5.2,-3.6) P17(6,-3.6) P18(6.8,-3.6) R1(-6.8,-4.4) R2(-6,-4.4) R3(-5.2,-4.4) R4(-4.4,-4.4) R5(-3.6,-4.4) R6(-2.8,-4.4) R7(-2,-4.4) R8(-1.2,-4.4) R9(-0.4,-4.4) R10(0.4,-4.4) R11(1.2,-4.4) R12(2,-4.4) R13(2.8,-4.4) R14(3.6,-4.4) R15(4.4,-4.4) R16(5.2,-4.4) R17(6,-4.4) R18(6.8,-4.4) T1(-6.8,-5.2) T2(-6,-5.2) T3(-5.2,-5.2) T4(-4.4,-5.2) T5(-3.6,-5.2) T6(-2.8,-5.2) T7(-2,-5.2) T8(-1.2,-5.2) T9(-0.4,-5.2) T10(0.4,-5.2) T11(1.2,-5.2) T12(2,-5.2) T13(2.8,-5.2) T14(3.6,-5.2) T15(4.4,-5.2) T16(5.2,-5.2) T17(6,-5.2) T18(6.8,-5.2) U1(-6.8,-6) U2(-6,-6) U3(-5.2,-6) U4(-4.4,-6) U5(-3.6,-6) U6(-2.8,-6) U7(-2,-6) U8(-1.2,-6) U9(-0.4,-6) U10(0.4,-6) U11(1.2,-6) U12(2,-6) U13(2.8,-6) U14(3.6,-6) U15(4.4,-6) U16(5.2,-6) U17(6,-6) U18(6.8,-6) V1(-6.8,-6.8) V2(-6,-6.8) V3(-5.2,-6.8) V4(-4.4,-6.8) V5(-3.6,-6.8) V6(-2.8,-6.8) V7(-2,-6.8) V8(-1.2,-6.8) V9(-0.4,-6.8) V10(0.4,-6.8) V11(1.2,-6.8) V12(2,-6.8) V13(2.8,-6.8) V14(3.6,-6.8) V15(4.4,-6.8) V16(5.2,-6.8) V17(6,-6.8) V18(6.8,-6.8)
BGA96_T9_P8_9X14
  round 0.356 smd: A1(-3.2,6.001) A2(-2.4,6.001) A3(-1.6,6.001) A7(1.6,6.001) A8(2.4,6.001) A9(3.2,6.001) B1(-3.2,5.201) B2(-2.4,5.201) B3(-1.6,5.201) B7(1.6,5.201) B8(2.4,5.201) B9(3.2,5.201) C1(-3.2,4.401) C2(-2.4,4.401) C3(-1.6,4.401) C7(1.6,4.401) C8(2.4,4.401) C9(3.2,4.401) D1(-3.2,3.6) D2(-2.4,3.6) D3(-1.6,3.6) D7(1.6,3.6) D8(2.4,3.6) D9(3.2,3.6) E1(-3.2,2.8) E2(-2.4,2.8) E3(-1.6,2.8) E7(1.6,2.8) E8(2.4,2.8) E9(3.2,2.8) F1(-3.2,2) F2(-2.4,2) F3(-1.6,2) F7(1.6,2) F8(2.4,2) F9(3.2,2) G1(-3.2,1.2) G2(-2.4,1.2) G3(-1.6,1.2) G7(1.6,1.2) G8(2.4,1.2) G9(3.2,1.2) H1(-3.2,0.4) H2(-2.4,0.4) H3(-1.6,0.4) H7(1.6,0.4) H8(2.4,0.4) H9(3.2,0.4) J1(-3.2,-0.4) J2(-2.4,-0.4) J3(-1.6,-0.4) J7(1.6,-0.4) J8(2.4,-0.4) J9(3.2,-0.4) K1(-3.2,-1.2) K2(-2.4,-1.2) K3(-1.6,-1.2) K7(1.6,-1.2) K8(2.4,-1.2) K9(3.2,-1.2) L1(-3.2,-2) L2(-2.4,-2) L3(-1.6,-2) L7(1.6,-2) L8(2.4,-2) L9(3.2,-2) M1(-3.2,-2.8) M2(-2.4,-2.8) M3(-1.6,-2.8) M7(1.6,-2.8) M8(2.4,-2.8) M9(3.2,-2.8) N1(-3.2,-3.6) N2(-2.4,-3.6) N3(-1.6,-3.6) N7(1.6,-3.6) N8(2.4,-3.6) N9(3.2,-3.6) P1(-3.2,-4.401) P2(-2.4,-4.401) P3(-1.6,-4.401) P7(1.6,-4.401) P8(2.4,-4.401) P9(3.2,-4.401) R1(-3.2,-5.201) R2(-2.4,-5.201) R3(-1.6,-5.201) R7(1.6,-5.201) R8(2.4,-5.201) R9(3.2,-5.201) T1(-3.2,-6.001) T2(-2.4,-6.001) T3(-1.6,-6.001) T7(1.6,-6.001) T8(2.4,-6.001) T9(3.2,-6.001)
BGA153_P14_P5_11P5X13
  round 0.254 smd: A1(-3.25,3.25) A2(-2.75,3.25) A3(-2.25,3.25) A4(-1.75,3.25) A5(-1.25,3.25) A6(-0.75,3.25) A7(-0.25,3.25) A8(0.25,3.25) A9(0.75,3.25) A10(1.25,3.25) A11(1.75,3.25) A12(2.25,3.25) A13(2.75,3.25) A14(3.25,3.25) B1(-3.25,2.75) B2(-2.75,2.75) B3(-2.25,2.75) B4(-1.75,2.75) B5(-1.25,2.75) B6(-0.75,2.75) B7(-0.25,2.75) B8(0.25,2.75) B9(0.75,2.75) B10(1.25,2.75) B11(1.75,2.75) B12(2.25,2.75) B13(2.75,2.75) B14(3.25,2.75) C1(-3.25,2.25) C2(-2.75,2.25) C3(-2.25,2.25) C4(-1.75,2.25) C5(-1.25,2.25) C6(-0.75,2.25) C7(-0.25,2.25) C8(0.25,2.25) C9(0.75,2.25) C10(1.25,2.25) C11(1.75,2.25) C12(2.25,2.25) C13(2.75,2.25) C14(3.25,2.25) D1(-3.25,1.75) D2(-2.75,1.75) D3(-2.25,1.75) D4(-1.75,1.75) D12(2.25,1.75) D13(2.75,1.75) D14(3.25,1.75) E1(-3.25,1.25) E2(-2.75,1.25) E3(-2.25,1.25) E5(-1.25,1.25) E6(-0.75,1.25) E7(-0.25,1.25) E8(0.25,1.25) E9(0.75,1.25) E10(1.25,1.25) E12(2.25,1.25) E13(2.75,1.25) E14(3.25,1.25) F1(-3.25,0.75) F2(-2.75,0.75) F3(-2.25,0.75) F5(-1.25,0.75) F10(1.25,0.75) F12(2.25,0.75) F13(2.75,0.75) F14(3.25,0.75) G1(-3.25,0.25) G2(-2.75,0.25) G3(-2.25,0.25) G5(-1.25,0.25) G10(1.25,0.25) G12(2.25,0.25) G13(2.75,0.25) G14(3.25,0.25) H1(-3.25,-0.25) H2(-2.75,-0.25) H3(-2.25,-0.25) H5(-1.25,-0.25) H10(1.25,-0.25) H12(2.25,-0.25) H13(2.75,-0.25) H14(3.25,-0.25) J1(-3.25,-0.75) J2(-2.75,-0.75) J3(-2.25,-0.75) J5(-1.25,-0.75) J10(1.25,-0.75) J12(2.25,-0.75) J13(2.75,-0.75) J14(3.25,-0.75) K1(-3.25,-1.25) K2(-2.75,-1.25) K3(-2.25,-1.25) K5(-1.25,-1.25) K6(-0.75,-1.25) K7(-0.25,-1.25) K8(0.25,-1.25) K9(0.75,-1.25) K10(1.25,-1.25) K12(2.25,-1.25) K13(2.75,-1.25) K14(3.25,-1.25) L1(-3.25,-1.75) L2(-2.75,-1.75) L3(-2.25,-1.75) L12(2.25,-1.75) L13(2.75,-1.75) L14(3.25,-1.75) M1(-3.25,-2.25) M2(-2.75,-2.25) M3(-2.25,-2.25) M4(-1.75,-2.25) M5(-1.25,-2.25) M6(-0.75,-2.25) M7(-0.25,-2.25) M8(0.25,-2.25) M9(0.75,-2.25) M10(1.25,-2.25) M11(1.75,-2.25) M12(2.25,-2.25) M13(2.75,-2.25) M14(3.25,-2.25) N1(-3.25,-2.75) N2(-2.75,-2.75) N3(-2.25,-2.75) N4(-1.75,-2.75) N5(-1.25,-2.75) N6(-0.75,-2.75) N7(-0.25,-2.75) N8(0.25,-2.75) N9(0.75,-2.75) N10(1.25,-2.75) N11(1.75,-2.75) N12(2.25,-2.75) N13(2.75,-2.75) N14(3.25,-2.75) P1(-3.25,-3.25) P2(-2.75,-3.25) P3(-2.25,-3.25) P4(-1.75,-3.25) P5(-1.25,-3.25) P6(-0.75,-3.25) P7(-0.25,-3.25) P8(0.25,-3.25) P9(0.75,-3.25) P10(1.25,-3.25) P11(1.75,-3.25) P12(2.25,-3.25) P13(2.75,-3.25) P14(3.25,-3.25)
DCK5_2P15X1P4
  rect 0.4x0.9 smd: 1(-0.65,-1.1) 2(0,-1.1) 3(0.65,-1.1) 4(0.65,1.1) 5(-0.65,1.1)
DGN-16X60
  oval 0.406x1.524 smd: 1(-0.975,-2.311) 2(-0.325,-2.311) 3(0.325,-2.311) 4(0.975,-2.311) 5(0.975,2.311) 6(0.325,2.311) 7(-0.325,2.311) 8(-0.975,2.311)
  rect 2.032x2.032 smd: 9(0,0)
HEADER10X2_SMD
  rect 0.711x2.794 smd: 1(-5.715,-2.705) 2(-5.715,2.705) 3(-4.445,-2.705) 4(-4.445,2.705) 5(-3.175,-2.705) 6(-3.175,2.705) 7(-1.905,-2.705) 8(-1.905,2.705) 9(-0.635,-2.705) 10(-0.635,2.705) 11(0.635,-2.705) 12(0.635,2.705) 13(1.905,-2.705) 14(1.905,2.705) 15(3.175,-2.705) 16(3.175,2.705) 17(4.445,-2.705) 18(4.445,2.705) 19(5.715,-2.705) 20(5.715,2.705)
HEADER23X2
  rect 1.524x1.524 hole 0.889: 1(0,0)
  round 1.524 hole 0.889: 2(0,2.54) 3(2.54,0) 4(2.54,2.54) 5(5.08,0) 6(5.08,2.54) 7(7.62,0) 8(7.62,2.54) 9(10.16,0) 10(10.16,2.54) 11(12.7,0) 12(12.7,2.54) 13(15.24,0) 14(15.24,2.54) 15(17.78,0) 16(17.78,2.54) 17(20.32,0) 18(20.32,2.54) 19(22.86,0) 20(22.86,2.54) 21(25.4,0) 22(25.4,2.54) 23(27.94,0) 24(27.94,2.54) 25(30.48,0) 26(30.48,2.54) 27(33.02,0) 28(33.02,2.54) 29(35.56,0) 30(35.56,2.54) 31(38.1,0) 32(38.1,2.54) 33(40.64,0) 34(40.64,2.54) 35(43.18,0) 36(43.18,2.54) 37(45.72,0) 38(45.72,2.54) 39(48.26,0) 40(48.26,2.54) 41(50.8,0) 42(50.8,2.54) 43(53.34,0) 44(53.34,2.54) 45(55.88,0) 46(55.88,2.54)
LED_0603
  rect 0.762x1.016 smd: 1(-0.826,0) 2(0.826,0)
MTGH200C125D_PL
  round 4.445 hole 3.175: 1(0,0)
OSC4_61X65LS_79X98SMD
  rect 0.711x0.889 smd: 1(-0.826,-0.775) 2(0.826,-0.775) 3(0.826,0.775) 4(-0.826,0.775)
QFN32_5X5MM_EP3P3MM
  oval 0.254x0.838 smd: 1(-1.751,-2.515) 8(1.751,-2.515) 17(1.751,2.515) 24(-1.751,2.515)
  rect 0.254x0.838 smd: 2(-1.251,-2.515) 3(-0.751,-2.515) 4(-0.25,-2.515) 5(0.25,-2.515) 6(0.751,-2.515) 7(1.251,-2.515) 18(1.251,2.515) 19(0.751,2.515) 20(0.25,2.515) 21(-0.25,2.515) 22(-0.751,2.515) 23(-1.251,2.515)
  oval 0.838x0.254 smd: 9(2.515,-1.751) 16(2.515,1.751) 25(-2.515,1.751) 32(-2.515,-1.751)
  rect 0.838x0.254 smd: 10(2.515,-1.251) 11(2.515,-0.751) 12(2.515,-0.25) 13(2.515,0.25) 14(2.515,0.751) 15(2.515,1.251) 26(-2.515,1.251) 27(-2.515,0.751) 28(-2.515,0.25) 29(-2.515,-0.25) 30(-2.515,-0.751) 31(-2.515,-1.251)
  rect 3.404x3.404 smd: 33(0,0)
RD205SMD_250D
  rect 3.048x1.651 smd: 1(-2.603,0) 2(2.603,0)
RJ45-7499010211A
  round 1.016 hole 3.251 unplated: (-1.27,-6.35) (10.16,-6.35)
  rect 1.524x1.524 hole 1.016: 1(0,0)
  round 1.524 hole 1.016: 2(1.27,2.54) 3(2.54,0) 4(3.81,2.54) 5(5.08,0) 6(6.35,2.54) 7(7.62,0) 8(8.89,2.54) 9(-1.88,-11.252) 10(0.66,-9.728) 11(8.23,-11.252) 12(10.77,-9.728)
  round 2.286 hole 1.6: 13(-3.429,-3.302) 14(12.319,-3.302)
SD-MICRO-SCHA5B0300
  rect 0.914x0.457 smd: 1(-7.257,0) 2(-7.257,-0.7) 3(-7.257,-1.4) 4(-7.257,-2.1) 5(7.257,-2.1) 6(7.257,-1.4) 7(7.257,-0.7) 8(7.257,0)
  rect 0.508x0.889 smd: 9(3.775,9.989) 10(-5.975,9.989)
  rect 0.889x2.007 smd: 11(-7.25,7.635) 12(7.25,6.335)
  rect 1.118x1.524 smd: 13(-7.196,-3.365) 14(7.196,-3.365)
  rect 1.194x1.092 smd: 15(-3.425,10.488) 16(2.575,10.488)
SIP6
  rect 1.524x1.524 hole 1.016: 1(0,0)
  round 1.524 hole 1.016: 2(0,-2.54) 3(0,-5.08) 4(0,-7.62) 5(0,-10.16) 6(0,-12.7)
SM-7351-IND-0805
  rect 1.397x1.549 smd: 1(-0.95,0) 2(0.95,0)
SM-7351-RES-0402
  round 0.635 smd: 1(-0.508,0) 2(0.508,0)
SMINI6-F3-B
  rect 0.305x0.95 smd: 1(0.65,0.75) 2(0,0.75) 3(-0.65,0.75) 4(-0.65,-0.75) 5(0,-0.75) 6(0.65,-0.75)
SO8-25X75
  oval 0.635x1.905 smd: 1(-1.905,-2.794) 2(-0.635,-2.794) 3(0.635,-2.794) 4(1.905,-2.794) 5(1.905,2.794) 6(0.635,2.794) 7(-0.635,2.794) 8(-1.905,2.794)
SOT23-5
  rect 0.635x1.016 smd: 1(-0.953,-1.295) 2(0,-1.295) 3(0.953,-1.295) 4(0.953,1.295) 5(-0.953,1.295)
SW_4P
  rect 1.422x0.813 smd: 1(-1.8,-0.94) 2(-1.8,0.94) 3(1.8,-0.94) 4(1.8,0.94)
TDFN8_P5_2P0
  rect 1.219x0.61 smd: (0,0)
  rect 0.305x0.711 smd: 1(-0.75,-0.85) 2(-0.25,-0.85) 3(0.25,-0.85) 4(0.75,-0.85) 5(0.75,0.85) 6(0.25,0.85) 7(-0.25,0.85) 8(-0.75,0.85)
TP1-8040
  round 1.524 hole 1.016: 1(0,0)
TP60C33D
  round 1.524 hole 0.889: 1(0,0)
TP60C_SMD
  round 1.27 smd: 1(0,0)
U_6_DRY
  rect 0.305x0.508 smd: 1(-0.5,-0.439) 2(0,-0.439) 3(0.5,-0.439) 4(0.5,0.439) 5(0,0.439) 6(-0.5,0.439)
U_8_DCU
  rect 0.254x1.27 smd: 1(-0.749,-1.473) 2(-0.249,-1.473) 3(0.249,-1.473) 4(0.749,-1.473) 5(0.749,1.473) 6(0.249,1.473) 7(-0.249,1.473) 8(-0.749,1.473)
U_48_RSL
  rect 0.8x0.2 smd: 1(-3.075,2.2) 2(-3.075,1.8) 3(-3.075,1.4) 4(-3.075,1) 5(-3.075,0.6) 6(-3.075,0.2) 7(-3.075,-0.2) 8(-3.075,-0.6) 9(-3.075,-1) 10(-3.075,-1.4) 11(-3.075,-1.8) 12(-3.075,-2.2) 25(3.075,-2.2) 26(3.075,-1.8) 27(3.075,-1.4) 28(3.075,-1) 29(3.075,-0.6) 30(3.075,-0.2) 31(3.075,0.2) 32(3.075,0.6) 33(3.075,1) 34(3.075,1.4) 35(3.075,1.8) 36(3.075,2.2)
  rect 0.2x0.8 smd: 13(-2.2,-3.075) 14(-1.8,-3.075) 15(-1.4,-3.075) 16(-1,-3.075) 17(-0.6,-3.075) 18(-0.2,-3.075) 19(0.2,-3.075) 20(0.6,-3.075) 21(1,-3.075) 22(1.4,-3.075) 23(1.8,-3.075) 24(2.2,-3.075) 37(2.2,3.075) 38(1.8,3.075) 39(1.4,3.075) 40(1,3.075) 41(0.6,3.075) 42(0.2,3.075) 43(-0.2,3.075) 44(-0.6,3.075) 45(-1,3.075) 46(-1.4,3.075) 47(-1.8,3.075) 48(-2.2,3.075)
  rect 4.05x4.05 smd: 49(-0.225,0.225)
unnamed#2
  round 1.016 smd: 1(0,0)
unnamed#3
  round 2.032 hole 2.032 unplated: (0,0)
USB-003A-4P-90D
  rect 1.321x1.321 hole 0.914: 1(-3.5,2.71)
  round 1.321 hole 0.914: 2(-1,2.71) 3(1,2.71) 4(3.5,2.71)
  round 2.946 hole 2.337: 5(-6.57,0) 6(6.57,0)
XTAL4_126-216SMD
  rect 1.27x1.905 smd: 1(-2.748,-1.6) 2(2.751,-1.6) 3(2.751,1.6) 4(-2.748,1.6)
XTAL150SMD_125X196
  rect 1.778x2.159 smd: 1(-1.9,0) 2(1.9,0)

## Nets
DGND: C1.1 C2.1 C3.1 C4.1 C7.1 C8.1 C9.1 C10.1 C11.1 C12.1 C13.1 C14.1 C15.1 C16.2 C17.2 C18.2 C19.2 C20.2 C24.2 C28.2 C29.2 C30.2 C34.2 C35.2 C36.2 C37.2 C38.2 C39.1 C40.1 C41.2 C42.2 C43.2 C44.2 C45.2 C46.2 C47.2 C48.2 C49.2 C50.2 C51.2 C52.2 C53.2 C54.2 C55.1 C56.1 C57.1 C58.2 C59.2 C60.1 C61.1 C62.1 C63.2 C64.2 C65.2 C66.2 C67.2 C68.1 C69.1 C70.1 C71.1 C72.1 C73.1 C74.1 C75.1 C76.1 C77.2 C78.2 C79.2 C80.2 C81.2 C82.2 C83.2 C84.2 C85.2 C86.2 C87.2 C88.2 C89.2 C90.2 C91.2 C92.2 C94.2 C95.1 C96.1 C97.2 C98.2 C99.2 C100.2 C101.2 C102.2 C103.2 C104.2 C105.2 C106.2 C107.2 C108.2 C109.2 C110.2 C111.2 C112.2 C113.2 C114.2 C115.2 C116.2 C117.2 C118.1 C119.2 C120.2 C121.2 C122.1 C123.2 C124.2 C125.2 C126.1 C127.2 C128.2 C129.2 C130.2 C131.2 C132.2 C133.1 C134.2 C135.2 C136.2 C137.2 C138.2 C139.2 C140.2 C141.2 C142.2 C143.2 C152.2 C153.2 C154.2 C155.1 C158.2 C159.2 C161.2 C162.1 FB3.2 J1.1 J4.4 J5.4 P2.4 P2.8 P2.10 P2.12 P2.16 P2.20 P3.4 P4.5 P5.8 P8.1 P8.2 P9.1 P9.2 P9.43 P9.44 P9.45 P9.46 P10.6(VSS) P10.9 Q1.1 Q1.4 Q2.1 Q2.4 R10.2 R12.1 R22.1 R25.2 R29.1 R30.1 R49.1 R53.2 R54.1 R76.2 R77.2 R78.2 R79.2 R80.2 R81.2 R82.2 R83.2 R84.2 R85.2 R86.2 R87.2 R88.2 R89.2 R90.2 R91.2 R92.2 R93.2 R94.2 R95.2 R96.1 R99.1 R100.2 R115.2 R116.2 R117.2 R118.2 R130.1 R132.1 R135.2 R136.1 R144.2 R145.2 R164.2 R165.2 R170.2 S1.1 S1.3 S2.2 S2.4(B2) S3.1 S3.3 TP1.1(TP) TP8.1(TP) U2.30 U2.41 U2.49 U3.3 U4.5 U4.6 U4.7 U4.8 U5.A1 U5.A18 U5.F8 U5.G8 U5.G9 U5.G11 U5.G12 U5.H6 U5.H7 U5.H8 U5.H9 U5.H10 U5.H12 U5.J6 U5.J7 U5.J8 U5.J9 U5.J10 U5.J11 U5.K7 U5.K9 U5.K10 U5.K11 U5.L10 U5.L11 U5.L12 U5.L13 U5.M6 U5.M7 U5.M8 U5.M9 U5.M10 U5.M12 U5.M14(VSSA_USB2) U5.N7 U5.N10 U5.N11 U5.N14 U5.V1 U5.V18 U7.2 U8.1 U8.9(PAD) U9.4 U10.4 U12.A9 U12.B1 U12.B3 U12.B9 U12.D1 U12.D8 U12.E1 U12.E2 U12.E8 U12.F9 U12.G1 U12.G8 U12.G9 U12.J2 U12.J8 U12.M1 U12.M9 U12.P1 U12.P9 U12.T1 U12.T9 U13.C4(VSSQ4) U13.E7 U13.G5 U13.H10 U13.K8 U13.N2 U13.N5 U13.P4 U13.P6 U14.33 U15.1 U15.4 U16.3 Y4.2
GND_EARTH: C163.2 C164.2 C165.2 C166.2 MTG1.1(TP) MTG2.1(TP) MTG3.1(TP) MTG4.1(TP) P3.5(SHELD1) P3.6 P4.6 P4.7 P4.8 P4.9 P5.13 P5.14 P10.11 P10.12 P10.13 P10.14 P10.15 P10.16 R136.2
GND_OSC0: C25.2 C26.2 R29.2 R173.2 R174.2 U5.V11 U17.4
GND_OSC1: C21.1 C22.1 R30.2 U5.A5
GNDA_ADC: C31.2 C32.2 C33.2 C93.2 FB3.1 P9.34 U5.A9 U5.E8
VBUS: FB7.2 P3.1
VDD_1V8: C14.2 C78.1 C86.1 C88.1 FB1.1 FB2.2 R9.2 U2.40 U5.D10 U5.E9 U5.N16 U5.R16
VDD_3V3A: C15.2 C37.1 C38.1 C56.2 C57.2 C58.1 C59.1 C60.2 C61.2 C66.1 C67.1 C68.2 C69.2 C70.2 C71.2 C72.2 C73.2 C74.2 C75.2 C76.2 C77.1 C87.1 C152.1 C158.1 C159.1 R1.1 R3.1 R4.1 R14.1 R52.1 R55.1 R56.1 R57.1 R58.1 R59.1 R60.1 R61.1 R62.1 R63.1 R64.1 R65.1 R66.1 R67.1 R68.1 R69.1 R70.1 R156.1 R169.2 R171.1 R172.1 R175.1 U2.43 U3.5 U4.1 U5.E10 U5.E11 U5.E12 U5.E13 U5.F14 U5.G14 U5.H14 U5.J14 U5.K14 U5.L14 U5.N5 U5.N15 U5.P5 U5.P6 U5.P7 U5.P8 U5.P10 U5.P11 U5.P12 U5.P13 U5.R15 U7.4 U17.8 Y4.4(VCC)
VDD_3V3AUX: C18.1 D1.2 U2.1
VDD_3V3B: C20.1 C29.1 C126.2 C127.1 C128.1 C129.1 C130.1 C135.1 C153.1 C154.1 C155.2 FB4.1 J4.3 J5.3 P2.5(TVDD) P9.3 P9.4 P10.4 R11.1 R23.1 R24.1 R101.1 R102.1 R103.1 R104.1 R105.1 R106.1 R107.1 R108.1 R109.1 R110.1 R111.1 R112.2 R113.2 R114.2 R119.1 R150.1 R151.1 R152.1 R153.1 R154.1 R155.1 R157.2 R163.1 U4.3(OUT) U13.C6 U13.E6 U13.F5 U13.J10 U13.K9 U13.M4 U13.N4 U13.P3 U13.P5 U14.12 U15.7 U15.8(VCC)
VDD_5V: C2.2 P9.5 P9.6 R168.2 U2.10
VDD_ADC: C93.1 FB2.1 P9.32 R27.1 U5.D8
VDD_CORE: C11.2 C39.2 C40.2 C41.1 C42.1 C43.1 C44.1 C45.1 C46.1 C47.1 C48.1 C49.1 C50.1 C51.1 C52.1 C53.1 C54.1 C55.2 L3.2 U2.29 U5.F6 U5.F7 U5.G6 U5.G7 U5.G10 U5.H11 U5.J12 U5.K6 U5.K8 U5.K12 U5.L6 U5.L7 U5.L8 U5.L9 U5.M11 U5.M13 U5.N8 U5.N9 U5.N12 U5.N13
VDD_MPU: C12.2 C62.2 C63.1 C64.1 C65.1 L2.2 U2.24 U5.F10 U5.F11 U5.F12 U5.F13 U5.G13 U5.H13 U5.J13
VDD_MPUON: TP2.1(TP) U5.A2
VDD_PHYA: C131.1 C132.1 C133.2 FB4.2 R120.2 R121.2 R122.2 R123.2 R137.2 U14.1 U14.27
VDD_PLL: C79.1 C92.1 C94.1 C106.1 FB1.2 U5.E7 U5.H15 U5.R10 U5.R11
VDD_RTC: C104.1 U5.D6
VDDS: C80.1 C81.1 C82.1 C83.1 C84.1 C85.1 R8.2 R9.1 U5.E6 U5.E14 U5.F9 U5.K13 U5.N6 U5.P9 U5.P14
VDDS_DDR: C9.2 C95.2 C96.2 C97.1 C98.1 C99.1 C100.1 C101.1 C102.1 C103.1 C107.1 C108.1 C109.1 C110.1 C111.1 C112.1 C113.1 C114.1 C115.1 C116.1 C117.1 C118.2 C119.1 C120.1 C121.1 C122.2 R6.2 R97.1 R98.1 U5.E5 U5.F5 U5.G5 U5.H5 U5.J5 U5.K5 U5.L5 U12.A1 U12.A8 U12.B2 U12.C1 U12.C9 U12.D2 U12.D9 U12.E9 U12.F1 U12.G7 U12.H2 U12.H9 U12.K2 U12.K8 U12.N1 U12.N9 U12.R1 U12.R9
AIN0: P9.39 U5.B6
AIN1: P9.40 U5.C7
AIN2: P9.37 U5.B7
AIN3: P9.38 U5.A7
AIN4: P9.33 U5.C8
AIN5: P9.36 U5.B8
AIN6: P9.35 U5.A8
AIN7: R163.2 R164.1 U5.C9
B_UART0_RX: J1.4 R165.1 U15.2
B_UART0_TX: J1.5 U15.3
CAP_VBB_MPU: C91.1 U5.C10
CAP_VDD_SRAM_CORE: C89.1 U5.D9
CAP_VDD_SRAM_MPU: C90.1 U5.D11
CLKOUT2: P2.18 P9.41 R19.2 R20.1
CLKOUT_SRC: R19.1 U5.D14
CRS: R139.2 U14.14
DDR_A0: U5.F3 U12.N3
DDR_A1: U5.H1 U12.P7
DDR_A2: U5.E4 U12.P3
DDR_A3: U5.C3 U12.N2
DDR_A4: U5.C2 U12.P8
DDR_A5: U5.B1 U12.P2
DDR_A6: U5.D5 U12.R8
DDR_A7: U5.E2 U12.R2
DDR_A8: U5.D4 U12.T8
DDR_A9: U5.C1 U12.R3
DDR_A10: U5.F4 U12.L7
DDR_A11: U5.F2 U12.R7
DDR_A12: U5.E3 U12.N7
DDR_A13: U5.H3 U12.T3
DDR_A14: U5.H4 U12.T7
DDR_A15: U5.D3 U12.M7
DDR_BA0: U5.C4 U12.M2
DDR_BA1: U5.E1 U12.N8
DDR_BA2: U5.B3 U12.M3
DDR_CASN: U5.F1 U12.K3
DDR_CKE: R96.2 U5.G3 U12.K9
DDR_CLK: U5.D2 U12.J7
DDR_CLKN: U5.D1 U12.K7
DDR_CSN: U5.H2 U12.L2
DDR_D0: U5.M3 U12.E3
DDR_D1: U5.M4 U12.F7
DDR_D2: U5.N1 U12.F2
DDR_D3: U5.N2 U12.F8
DDR_D4: U5.N3 U12.H3
DDR_D5: U5.N4 U12.H8
DDR_D6: U5.P3 U12.G2
DDR_D7: U5.P4 U12.H7
DDR_D8: U5.J1 U12.D7
DDR_D9: U5.K1 U12.C3
DDR_D10: U5.K2 U12.C8
DDR_D11: U5.K3 U12.C2
DDR_D12: U5.K4 U12.A7
DDR_D13: U5.L3 U12.A2
DDR_D14: U5.L4 U12.B8
DDR_D15: U5.M1 U12.A3
DDR_DQM0: U5.M2 U12.E7
DDR_DQM1: U5.J2 U12.D3
DDR_DQS0: U5.P1 U12.F3
DDR_DQS1: U5.L1 U12.C7
DDR_DQSN0: U5.P2 U12.G3
DDR_DQSN1: U5.L2 U12.B7
DDR_ODT: U5.G1 U12.K1
DDR_RASN: U5.G4 U12.J3
DDR_RESETN: R97.2 U5.G2 U12.T2
DDR_VREF: C28.1 C123.1 C124.1 R98.2 R100.1 U5.J4 U12.H1 U12.M8
DDR_VTP: R22.2 U5.J3
DDR_WEN: U5.B2 U12.L3
EHRPWM1A: P9.14 U5.U14
EHRPWM1B: P9.16 U5.T14
EHRPWM2A: P8.19 U5.U10
EHRPWM2B: P8.13 U5.T10
EMMC_RSTN: R111.2 R162.2 U13.K5
EMMC_VCCI: C125.1 U13.C2
ENZ_KALDO_1P8V: R54.2 U5.B4
ETH_TXD4: R145.1 U14.18
GPIO0_7: P9.42 R50.1 R51.1
GPIO0_7SRC: R50.2 U5.C18
GPIO0_26: P8.14 U5.T11
GPIO0_27: P8.17(9) U5.U12
GPIO1_12: P8.12 U5.T12
GPIO1_13: P8.11 U5.R12
GPIO1_14: P8.16 U5.V13
GPIO1_15: P8.15 U5.U13
GPIO1_16: P9.15 R160.2 R161.2
GPIO1_17: P9.23 U5.V14
GPIO1_28: P9.12 U5.U18
GPIO1_29: P8.26 U5.V6
GPIO2_1: P8.18 U5.V12
GPIO3_18: R51.2 U5.B12
GPIO3_19: P9.27 U5.C13
GPIO3_20: R20.2 U5.D13
GPIO3_21: P9.25 R167.2 U5.A14
GRN_C: P5.10 R132.2
GRNA: C163.1 C165.1 P5.9 U14.3
HDMI_INT: R169.1 R170.1 U5.U16
HDMICLK_DISN: U5.V17 Y4.1
I2C0_SCL: R3.2 U2.28 U5.C16 U7.1
I2C0_SDA: R4.2 U2.27 U5.C17 U7.3
I2C1_SCL: P9.17(9) U5.A16
I2C1_SDA: P9.18 U5.B16
I2C2_SCL: J4.1 P9.19 U5.D17
I2C2_SDA: J4.2 P9.20 U5.D18
JTAG_EMU0: P2.13 R23.2 U5.C14
JTAG_EMU1: P2.14 R24.2 U5.B14
JTAG_TCK: P2.9 P2.11 U5.A12
JTAG_TDI: P2.3 U5.B11
JTAG_TDO: P2.7 U5.A11
JTAG_TMS: P2.1 U5.C11
JTAG_TRSTN: P2.2 R25.1 U5.B10
LCD_DATA0: P8.45 R70.2 R95.1 U5.R1
LCD_DATA1: P8.46 R69.2 R94.1 U5.R2
LCD_DATA2: P8.43 R68.2 R75.1 R93.1 U5.R3
LCD_DATA3: P8.44 R67.2 R92.1 U5.R4
LCD_DATA4: P8.41 R66.2 R91.1 U5.T1
LCD_DATA5: P8.42 R65.2 R90.1 U5.T2
LCD_DATA6: P8.39 R64.2 R89.1 U5.T3
LCD_DATA7: P8.40 R63.2 R88.1 U5.T4
LCD_DATA8: P8.37 R62.2 R87.1 U5.U1
LCD_DATA9: P8.38 R61.2 R86.1 U5.U2
LCD_DATA10: P8.36 R60.2 R85.1 U5.U3
LCD_DATA11: P8.34 R59.2 R84.1 U5.U4
LCD_DATA12: P8.35 R58.2 R83.1 U5.V2
LCD_DATA13: P8.33 R57.2 R82.1 U5.V3
LCD_DATA14: P8.31 R56.2 R81.1 U5.V4
LCD_DATA15: P8.32 R55.2 R80.1 U5.T5
LCD_DE: P8.30 R48.2
LCD_HSYNC: P8.29 R47.2
LCD_PCLK: P8.28 R45.2
LCD_VSYNC: P8.27 R46.2
LCDDE: R48.1 U5.R6
LCDPCLK: R45.1 U5.V5
LCDVHYNC: R47.1 U5.R5
LCDVSYNC: R46.1 U5.U5
LDO_PGOOD: U2.46 U5.B5
LEDAA: D2.2 R72.2
LEDAC: D2.1(C) Q1.6
LEDBA: D3.2 R73.2
LEDBC: D3.1(C) Q1.3
LEDCA: D4.2 R74.2
LEDCC: D4.1(C) Q2.6
LEDDA: D5.2 R71.2
LEDDC: D5.1(C) Q2.3
MDIO_CLK: U5.M18 U14.17
MDIO_DATA: R119.2 U5.M17 U14.16
MII1_COL: R138.1 U5.H16
MII1_CRS_DV: R139.1 U5.H17
MII1_REFCLK: R28.2 R124.1 R140.1
MII1_RXCLK: R131.1 U5.L18
MII1_RXD0: R128.1 U5.M16
MII1_RXD1: R127.1 U5.L15
MII1_RXD2: R126.1 U5.L16
MII1_RXD3: R125.1 U5.L17
MII1_RXDV: R129.1 U5.J17
MII1_RXERR: R133.1 U5.J15
MII1_TXCLK: R134.1 U5.K18
MII1_TXD0: U5.K17 U14.22
MII1_TXD1: U5.K16 U14.23
MII1_TXD2: U5.K15 U14.24
MII1_TXD3: U5.J18 U14.25
MII1_TXEN: U5.J16 U14.21
MMC0_CD: P2.19 P10.10 R157.1 U5.C15
MMC0_CLKO: P10.5 R152.2 U5.G17
MMC0_CMD: P10.3 R151.2 U5.G18
MMC0_DAT0: P10.7 R153.2 U5.G16
MMC0_DAT1: P10.8 R154.2 U5.G15
MMC0_DAT2: P10.1 R150.2 U5.F18
MMC0_DAT3: P10.2 R155.2 U5.F17
MMC1_CLK: P8.21 R110.2 U5.U9 U13.M6
MMC1_CMD: P8.20 R109.2 U5.V9 U13.M5
MMC1_DAT0: P8.25 R101.2 U5.U7 U13.A3
MMC1_DAT1: P8.24 R102.2 U5.V7 U13.A4
MMC1_DAT2: P8.5 R103.2 U5.R8 U13.A5
MMC1_DAT3: P8.6 R104.2 U5.T8 U13.B2
MMC1_DAT4: P8.23 R105.2 U5.U8 U13.B3
MMC1_DAT5: P8.22 R106.2 U5.V8 U13.B4
MMC1_DAT6: P8.3 R107.2 U5.R9 U13.B5
MMC1_DAT7: P8.4 R108.2 U5.T9 U13.B6
MODE2: R113.1 R138.2 U14.15
OSC1_IN: C21.2 U5.A6 Y1.1
OSC1_OUT: C22.2 U5.A4 Y1.4
P_BYPASS: C4.2 U2.47
P_INT_LDO: C3.2 U2.48
P_L1: L1.1 U2.20
P_L2: L2.1 U2.23
P_L3: L3.1 U2.31
PHY_VDDCR: C134.1 C136.1 U14.6
PHY_XTAL1: C143.1 R141.2 R142.1 Y3.1
PHY_XTAL2: R141.1 R143.1 U14.4(XTAL2)
PHYX: C142.1 R143.2 Y3.2
PMIC_INT: R1.2 U2.45 U5.B18
PMIC_PGOOD: U2.26 U5.B15 U16.2
PMIC_POWR_EN: U2.9 U5.C6
PROC_A15: R18.1 U5.A15
PWR_BUT: P9.9 S3.2 S3.4(B2) U2.25
PWR_LEDR: D1.1(C) R12.2
RBIAS: R144.1 U14.32
RCLKIN: C161.1 R140.2 R142.2 U14.5
REFCLKO: C162.2 R118.1 R124.2 R131.2 U14.7
RXD0/MODE0: R112.1 R128.2 U14.11
RXD1/MODE1: R114.1 R127.2 U14.10
RXD2/RMIISEL: R117.1 R126.2 U14.9
RXD3/PHYAD2: R116.1 R125.2 U14.8
RXDV: R129.2 U14.26
RXER/PHYAD0: R115.1 R133.2 U14.13
RXN: C138.1 P5.2 R121.1 U14.30
RXP: C137.1 P5.1 R120.1 U14.31
SPI1_CS0: P9.28 U5.C12
SPI1_D0: P9.29 U5.B13
SPI1_D1: P9.30 U5.D12
SPI1_SCLK: P9.31 U5.A13
SYS_5V: C7.2 C8.2 C10.2 C13.2 C17.1 C34.1 P9.7 P9.8 R71.1 R72.1 R73.1 R74.1 U2.2 U2.7 U2.8 U2.21 U2.22 U2.32 U2.39 U2.42 U4.2 U8.2 U8.3
SYS_RESETN: C24.1 C30.1 P2.15 P9.10 R14.2 S1.2 S1.4(B2) U5.A10 U14.19 U16.4(Y)
TCT_RCT: C141.1 P5.4 P5.5 R137.1
TESTOUT: TP3.1(TP) U5.A3
TIMER4: P8.7 U5.R7
TIMER5: P8.9 U5.T6
TIMER6: P8.10 U5.U6
TIMER7: P8.8 U5.T7
TXCLK: R134.2 U14.20
TXN: C140.1 P5.6 R123.1 U14.28
TXP: C139.1 P5.3 R122.1 U14.29
U5_H18: R28.1 U5.H18
U5_R13: R160.1 U5.R13
U5_T13: R161.1 U5.T13
UART0_RX: U5.E15 U15.6
UART0_TX: U5.E16 U15.5
UART1_RXD: P9.26 U5.D16
UART1_TXD: P9.24 U5.D15
UART2_RXD: J5.1 P9.22 U5.A17
UART2_TXD: J5.2 P9.21 U5.B17
UART4_RXD: P9.11 U5.T17
UART4_TXD: P9.13 U5.U17
USB0_DM: P4.2 U5.N18 U10.2
USB0_DP: P4.3 U5.N17 U10.1
USB0_ID: P4.4 U5.P16 U10.3
USB1_DM: P3.2 U5.R18 U9.2
USB1_DP: P3.3 U5.R17 U9.1
USB1_DRVVBUS: R53.1 U5.F15 U8.4
USB1_ID: R49.2 U5.P17
USB1_OCN: R52.2 U5.T16 U8.5
USB1_PWR: C35.1 FB7.1 FB8.2 U8.6 U8.7 U8.8 U9.6(VBUS)
USB1_VBUS: FB8.1 U5.T18
USB_DC: C1.2 C36.1 P4.1(VB) R159.1 R168.1 U2.12 U10.6(VBUS)
USR0: Q1.2 R76.1 U5.V15
USR1: Q1.5 R77.1 U5.U15
USR2: Q2.2 R78.1 U5.T15
USR3: Q2.5 R79.1 U5.V16
VDCDC1: L1.2 R6.1 U2.19
VIO: R7.2 U2.18 U16.5
VLDO1: R5.1 R7.1 R8.1 U2.3
VREFP_ADC: C31.1 C32.1 C33.1 R27.2 U5.B9
VRTC: C16.1 C105.1 R5.2 R26.1 U5.D7
WAKEUP: R26.2 U2.13(WAKEUP) U5.C5
WP: R156.2 TP4.1(TP) U7.5(WP)
XDMA_EVENT_INTR0: P2.17 R18.2
YEL_C: P5.11(YELC) R130.2
YELA: C164.1 C166.1 P5.12 R135.1 U14.2
ZQ: R99.2 U12.L8(ZQ)
N21757673: C19.1 R10.1 R11.2 U4.4
N21769115: R75.2 S2.1 S2.3
N22155575: R159.2 U5.P15
N22248684: R167.1 Y4.3
N22287501: R162.1 U3.4(Y)
N22287555: U3.2 U5.R14
N22420400: TP5.1(TP) U2.4 U2.5
N22420444: TP6.1(TP) U2.6
N22420447: TP7.1(TP) U2.11
N22488252: TP9.1(TP) U5.E17
N22648410: C25.1 R17.1 U17.1(XIN/CXIN) Y2.2
N22648422: C26.1 R17.2 U17.2 Y2.1
N22649826: R171.2 U17.3
N22650321: R172.2 R174.1 U17.6
N22650344: R173.1 R175.2 U17.7
N22650388: U5.V10 U17.5

Pads without a net: J1 2 3 6; NOREF#3 1; NOREF#9 1; NOREF#15 1; NOREF#22 1; NOREF#23 1; NOREF#27 1; NOREF#29 1; NOREF#32 1; NOREF#33 1; NOREF#35 1; NOREF#36 1; NOREF#37 1; NOREF#39 1; NOREF#40 1; P2 6; P5 7; U2 14 15 16 17 33 34 35 36 37 38 44; U3 1; U5 E18 F16 M5 M15 P18 U11; U9 3 5; U10 5; U12 J1 J9 L1 L9; U13 A1 A2 A6 A7 A8 A9 A10 A11 A12 A13 A14 B1 B7 B8 B9 B10 B11 B12 B13 B14 C1 C3 C5 C7 C8 C9 C10 C11 C12 C13 C14 D1 D2 D3 D4 D12 D13 D14 E1 E2 E3 E5 E8 E9 E10 E12 E13 E14 F1 F2 F3 F10 F12 F13 F14 G1 G2 G3 G10 G12 G13 G14 H1 H2 H3 H5 H12 H13 H14 J1 J2 J3 J5 J12 J13 J14 K1 K2 K3 K6 K7 K10 K12 K13 K14 L1 L2 L3 L12 L13 L14 M1 M2 M3 M7 M8 M9 M10 M11 M12 M13 M14 N1 N3 N6 N7 N8 N9 N10 N11 N12 N13 N14 P1 P2 P7 P8 P9 P10 P11 P12 P13 P14; U16 1; Y1 2 3

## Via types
v1: diameter 0.457, hole 0.203, TOP to BOTTOM, 820 vias
v2: diameter 0.559, hole 0.305, TOP to BOTTOM, 28 vias

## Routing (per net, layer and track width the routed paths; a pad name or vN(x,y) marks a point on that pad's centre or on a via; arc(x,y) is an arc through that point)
DGND: length 353.8
  TOP w0.076: U13.N2 27.09,44.66 26.84,44.91 26.49,44.91 26.48,44.92 26.33,44.92
  TOP w0.178: U13.N5 U13.P4
  TOP w0.191: U10.4 v1(14.1,41.41)
  TOP w0.203: v1(29.79,43.69) 29.79,43.46 29.95,43.31 U13.G5 ; v2(23.88,15.24) 24.26,15.24 24.46,15.04 U2.30 ; U13.H10 29.6,40.38 29.84,40.13 v1(29.84,40.06) ; v1(26.04,42.52) 26.18,42.66 U13.P6 ; v1(26.01,45.09) 26.17,44.92 26.33,44.92 ; v1(31.6,41.99) 31.27,41.99 U13.E7 ; U13.C4 v1(31.6,43.16) ; U13.P4 25.58,43.66 v1(25.1,44.15) ; U2.41 v1(23.46,19.62) ; U13.K8 v1(28.07,41.66)
  TOP w0.254: U5.M6 v1(48.12,30.81) U5.M7 ; U5.N10 v1(44.92,32.41) U5.N11 ; v1(43.32,27.61) U5.H12 ; v1(60.7,27.17) U12.E1 60.18,27.69 59.69,27.69 59.31,27.3 59.31,26.96 U12.G1 ; v1(52.6,36.58) 52.52,36.49 U5.V1 ; U5.A1 v1(52.52,21.72) ; U5.L13 v1(43.32,30.81) U5.L12 ; v1(61.5,30.37) U12.B3 ; v1(47.32,28.41) U5.J8 ; U5.M12 v1(44.12,30.81) U5.L11 ; U5.N14 v1(41.72,31.61) U5.M14 ; v1(48.12,28.41) U5.J7 U5.K7 ; U5.A18 v1(38.52,22.01) ; U5.H9 v1(46.52,27.61) U5.G8 ; U5.G9 v1(46.52,26.81) U5.F8 ; v1(44.92,31.61) U5.M10 ; U5.G11 44.36,27.05 43.88,27.05 U5.G12 v1(43.32,26.81) ; U12.B9 v1(67.1,30.37) U12.A9 ; U12.G9 v1(67.1,26.37) U12.F9 ; U5.M9 v1(46.52,31.61) U5.M8 ; v1(67.1,18.36) U12.T9 ; U5.V18 38.99,36.08 v1(38.99,36.83) ; v1(46.52,28.41) U5.J9 ; U5.L10 v1(44.92,30.01) ; v1(44.92,30.01) U5.K11 ; v1(44.92,30.01) U5.K10 ; v1(47.32,27.61) U5.H8 ; U12.E2 v1(60.7,27.97) U12.D1 ; U5.J10 v1(44.92,28.41) U5.H10 ; v1(46.52,30.01) U5.K9 ; v1(66.3,27.97) U12.E8 ; v1(66.3,28.77) U12.D8 ; U5.J6 v1(48.92,28.41) U5.H6 ; U5.H7 v1(48.12,27.61) ; v1(59.9,18.36) U12.T1 ; v1(59.9,30.37) U12.B1 ; v1(66.3,26.37) U12.G8 ; v1(67.1,19.96) U12.P9 ; U5.J11 v1(44.12,28.41) ; v1(48.12,32.41) U5.N7 ; v1(67.1,21.56) U12.M9 ; v1(60.7,23.96) U12.J2 ; v1(59.9,21.56) U12.M1 ; v1(59.9,19.96) U12.P1 ; v1(66.3,23.96) U12.J8
  TOP w0.381: v1(30.25,9.91) 30.66,9.91 30.88,9.69 U16.3 ; v1(30.68,24.74) 30.53,24.89 R118.2 C162.1 ; C18.2 v1(18.29,19.56) ; 56.52,12.8 56.49,12.83 C96.1 C155.1 55.63,11.68 55.73,11.68 v1(56.01,11.4) ; v1(20.95,7.24) 20.95,8.26 C1.1 21.59,8.13 v1(21.59,7.24) ; v1(73.79,45.85) 74.17,46.23 R94.2 ; 38.73,39.62 38.61,39.75 C159.2 37.59,39.75 37.34,40.01 ; 21.97,43.05 R77.2 21.72,44.45 21.34,44.83 21.34,45.34 v1(21.21,45.47) 20.7,45.47 20.59,45.35 Q1.4 ; R84.2 v1(56.26,45.72) ; S3.3 v1(8.89,39.73) ; 21.46,20.32 21.46,20.7 v1(22.1,21.34) ; v1(15.93,43.87) 16.41,43.87 16.62,43.65 Q2.1 ; v1(53.09,42.67) 52.96,42.8 R81.2 ; v1(21.31,38) 21.62,37.69 R170.2 ; S2.2 v1(75.69,42.75) ; v1(36.07,8.57) 36.07,8.76 36.39,9.08 R25.2 ; v1(21.08,39.6) 20.57,40.11 R79.2 R78.2 ; R95.2 75.95,46.23 v1(76.45,45.72) ; C154.2 v1(78.74,43.43) ; v1(78.41,15.54) J4.4 v1(74.37,15.54) ; v1(8.64,44.45) 7.95,43.76 S3.1 ; S1.3 v1(7.95,50.47) ; v1(34.29,6.48) C29.2 ; v1(83.06,43.81) 82.8,43.56 C153.2 ; Q1.1 19.29,43.63 v1(18.57,44.35) 18.44,44.48 18.08,44.48 17.92,44.64 Q2.4 ; C57.1 v1(54.86,48.51) ; v1(26.35,7.11) 26.29,7.18 26.29,8 26.61,8.32 C12.1 26.99,8.19 v1(26.99,7.11) ; U3.3 v1(40.97,45.72) ; J5.4 v1(78.53,30.4) ; C61.1 v1(75.06,48.39) ; v1(46.35,12.59) R165.2 ; R80.2 v1(53.98,45.85) ; v1(71.75,45.72) 72.39,46.35 R92.2 R93.2 ; S2.4 v1(72.14,42.75) ; S1.1 v1(7.95,51.36)
  TOP w0.889: Y4.2 41.43,42.1 ; Y4.2 40.78,42.66 ; Y4.2 40.78,41.54
  LYR2_GND w0.889: 16.41,24.67 P5.8 ; P5.8 16.41,26.13 ; P5.8 17.88,26.13 ; P5.8 17.88,24.67 ; TP8.1 18.01,7.39 ; TP8.1 16.54,7.39 ; TP8.1 18.01,8.86 ; TP8.1 16.54,8.86 ; 72.29,3.71 P9.44 ; P9.44 73.76,3.71 ; P9.44 72.29,5.18 ; P9.44 73.76,5.18 ; 41.58,6.65 J1.1 ; J1.1 43.51,6.65 ; J1.1 41.58,8.59 ; 9.62,8.97 P3.4 ; P3.4 10.95,8.97 ; P3.4 9.62,7.65 ; P3.4 10.95,7.65 ; 74.83,5.18 P9.46 ; P9.46 74.83,3.71 ; P9.46 76.3,5.18 ; P9.46 76.3,3.71 ; 72.29,2.64 P9.43 73.76,2.64 ; 20.65,2.87 P9.1 18.72,2.87 ; P8.1 20.65,51.13 ; P8.1 18.72,51.13 ; P8.1 20.65,49.2 ; P8.1 18.72,49.2 ; TP1.1 60.91,9.93 ; TP1.1 59.44,11.4 ; TP1.1 59.44,9.93 ; TP1.1 60.91,11.4 ; 18.95,5.18 P9.2 ; P9.2 20.42,3.71 ; P9.2 20.42,5.18 ; P9.2 18.95,3.71 ; 76.3,2.64 P9.45 74.83,2.64 ; 20.42,51.97 P8.2 18.95,51.97
  LYR5_PWR w0.889: 72.29,2.64 P9.43 73.76,2.64 ; 72.29,5.18 P9.44 ; P9.44 73.76,5.18 ; P9.44 73.76,3.71 ; P9.44 72.29,3.71 ; P9.46 76.3,3.71 ; P9.46 74.83,5.18 ; P9.46 74.83,3.71 ; P9.46 76.3,5.18 ; 74.83,2.64 P9.45 76.3,2.64
  BOTTOM w0.191: v1(44.92,24.41) 44.92,24.3 45.71,23.5 C88.2 ; R115.2 30.99,32.1 30.86,32.23 29.34,32.23 29.21,32.35 v1(29.21,32.7)
  BOTTOM w0.203: C100.2 48.81,25.94 49.26,25.5 49.43,25.5 v1(49.72,25.21)
  BOTTOM w0.254: C129.2 31.11,41.4 31.6,41.88 v1(31.6,41.99) ; C127.2 v1(25.4,40.64) ; v1(56.01,11.4) 56.01,11.68 55.75,11.94 C155.1 ; 52.29,17.22 R30.1 53.12,17.22 ; C128.2 28.96,42.42 28.23,41.69 28.09,41.69 v1(28.07,41.66) ; 14.1,17.02 v1(13.21,17.02) ; v1(43.32,27.61) v1(43.32,26.81) 42.63,26.12 C70.1 ; v1(12.83,15.75) 13.22,15.36 U9.4 ; v1(54.48,10.16) 53.21,10.16 52.83,10.54 52.83,11.43 52.08,12.18 U15.4 50.28,12.18 50.04,11.94 50.04,10.92 50.28,10.68 U15.1 ; C130.2 34.98,40.72 v1(35.59,40.72)
  BOTTOM w0.305: C66.2 41.72,30.92 v1(41.72,31.61) 41.72,32.3 C41.2 ; v1(44.92,30.01) 44.63,29.72 C46.2 ; v1(46.52,26.81) 46.23,26.52 C72.1 ; v1(44.92,28.41) 45.58,28.41 C49.2 ; C94.2 v1(44.12,30.81) ; C73.1 v1(48.12,32.41) 47.43,32.41 C43.2 ; v2(51.69,46.23) R29.1 v2(50.93,45.34) ; v1(48.12,30.81) C97.2 ; C48.2 47.83,28.7 v1(48.12,28.41) ; C50.2 v1(47.32,27.61) ; v1(46.52,30.01) 45.83,30.01 C47.2 ; C60.1 v1(43.32,27.61) ; C99.2 v1(48.12,27.61) ; v1(48.92,28.41) 48.92,29.1 C98.2 ; C63.2 44.01,26.81 v1(43.32,26.81) ; C42.2 46.23,31.9 v1(46.52,31.61)
  BOTTOM w0.381: R144.2 v1(18.73,28.26) ; R96.1 v1(69.85,23.16) ; C110.2 v1(57.15,25.57) 57.06,25.65 R22.1 ; C126.1 23.5,40.13 v1(23.6,40.03) ; C136.2 26.16,30.23 25.91,30.48 ; C71.1 38.86,36.96 v1(38.99,36.83) ; v1(69.88,25.04) 69.35,25.57 C117.2 ; R54.1 51.12,18.66 50.87,18.41 v1(49.21,18.41) ; R53.2 v1(2.92,5.21) ; U7.2 29.91,21.91 29.46,21.46 v1(29.46,20.7) ; R91.2 v1(67.77,44.07) R90.2 ; C74.1 50.52,37.74 v1(50.16,38.1) ; v1(59.11,43.76) 59.41,44.07 R82.2 ; C56.1 v1(45.72,36.83) 44.45,36.83 43.96,37.32 C106.2 C58.2 ; v1(6.22,29.46) v1(6.22,30.23) ; v1(6.22,29.46) R130.1 R135.2 ; v1(6.22,29.46) 5.4,29.46 R136.1 5.4,30.23 v1(6.22,30.23) ; v1(6.22,30.23) R132.1 ; C28.2 v1(57.15,28.41) ; R100.2 C124.2 v1(62.99,21.21) ; C109.2 v1(57.15,27.17) ; C19.2 17.02,37.8 v1(17.42,37.39) ; C122.1 69.84,16.83 v1(69.85,16.82) ; C38.2 C67.2 v1(33.02,35.56) ; C121.2 v1(69.85,19.16) ; 33.02,20.33 33.78,20.33 ; 33.02,20.33 v1(33.02,20.32) ; 33.02,20.33 33.02,21.21 C62.1 33.78,21.21 33.78,20.33 ; 33.78,20.33 C64.2 ; C86.2 37.58,35.24 37.21,35.61 36.75,35.61 v1(36.7,35.66) ; R49.1 37.15,33.97 v1(36.83,33.66) ; R87.2 v1(64.14,43.31) ; v1(49.21,18.41) C104.2 C92.2 ; v1(49.21,18.41) R164.2 ; C78.2 35.05,33.91 v1(35.56,33.91) ; P4.5 4.69,45.39 3.38,45.39 v1(3.07,45.69) ; v1(16.54,37.41) 16.13,37.82 R10.2 ; C140.2 v1(10.67,27.94) ; R88.2 v1(65.02,43.31) ; C141.2 v1(10.67,30.48) ; v1(41.35,38) 41.35,37.81 41.32,37.78 C80.2 ; C85.2 C83.2 C82.2 36.96,24.77 36.84,24.89 v1(36.83,24.89) ; v1(1.91,17.78) 2.29,17.4 R12.1 ; C92.2 v1(48.26,18.53) ; C92.2 C105.2 C89.2 C91.2 C90.2 C59.2 ; v1(66.3,23.96) U12.J8 C123.2 ; R99.1 v1(69.85,21.96) ; R85.2 v1(61.98,43.33) ; v1(19.79,37.49) 20.32,38.02 C17.2 ; R83.2 60.71,43.54 v1(61.01,43.23) ; C118.1 70.1,26.11 v1(69.93,25.93) ; C120.2 v1(69.85,20.76) ; v1(18.69,48.62) 18.16,48.08 U4.6 ; C45.2 C87.2 37.55,30.77 36.87,30.77 v1(36.83,30.81) ; P10.6 v1(83,31.58) ; v1(18.14,49.45) 17.91,49.45 16.89,48.44 U4.5 ; R30.1 C102.2 ; C111.2 v1(57.15,23.16) ; C113.2 v1(57.15,19.16) ; R89.2 v1(66.29,43.33) ; C125.2 v1(32.38,48.26) ; C114.2 v1(69.85,31.17) ; C54.2 C79.2 C69.1 ; C54.2 v1(36.83,26.81) ; C54.2 C44.2 ; C139.2 v1(10.67,31.75) ; C142.2 v1(21.91,25.27) ; C81.2 47.88,37.54 v1(47.32,38.1) 46.99,37.77 C84.2 ; v1(18.87,37.39) 19.18,37.69 C20.2 ; C115.2 v1(69.85,29.57) ; C161.2 27.18,27.18 v1(27.94,27.18) ; v1(27.99,33.63) 27.84,33.63 27.81,33.66 C135.2 ; C108.2 v1(57.15,29.57) ; v1(14.27,11.86) 14.27,12.4 14.78,12.9 C2.1 v1(15.34,11.81) ; P2.20 39.56,18.73 40.53,17.76 40.53,16.27 40.24,15.98 39.5,15.98 39.35,16.13 38.01,16.13 P2.16 v1(36.07,16.19) ; v1(32.38,37.15) C77.2 ; C75.1 v1(53.09,48.39) ; C158.2 40.51,47.5 40.97,47.04 v1(40.97,45.72) ; R86.2 v1(62.87,43.23) ; P2.12 P2.10 36.32,12.38 36.07,12.13 v1(36.07,11.18) 36.13,11.11 P2.8 ; R145.2 v1(31.75,34.61) ; R117.2 R116.2 v1(31.75,27.94) ; C61.1 v1(75.06,48.39) ; C24.2 C30.2 30,10.16 v1(30.25,9.91) ; U8.1 4.91,9.36 5.33,9.78 v1(5.59,9.78) ; C137.2 11.77,34.07 11.77,33.91 12.02,33.66 v1(12.06,33.66) ; C68.1 v1(48.92,38.1) ; P10.9 v1(72.6,33.94) ; v1(13.21,44.45) 13.46,44.2 C36.2 v1(12.67,43.69) ; C119.2 v1(69.85,24.36) ; C152.2 v1(26.04,23.11) ; C35.2 v1(6.1,16) ; C138.2 v1(10.67,33.02) ; U4.7 v1(19.43,48.39) ; C112.2 v1(57.15,20.76) ; C107.2 v1(57.15,31.17) ; U4.8 v1(20.7,48.39) ; P2.4 v1(36.07,8.57) ; C116.2 v1(69.98,28.57) ; v1(44.2,14.1) v1(43.43,14.1) 43.43,14.86 FB3.2 44.2,14.86 v1(44.2,14.1)
  BOTTOM w0.762: P8.1 P8.2 ; P9.1 P9.2 ; P9.45 P9.46
  vias: v1(3.81,32.13) v1(6.99,28.7) v1(10.31,44.45) v1(13.11,19.38) v1(13.13,18.16) v1(15.62,16.26) v1(21.91,26.35) v1(24.64,24.46) v1(28.32,24.51) v1(28.57,2.13) v1(29.97,18.03) v1(29.97,17.4) v1(31.06,2.08) v1(33.02,27.37) v1(33.02,26.54) v1(33.02,24.38) v1(40.01,42.77) v1(40.64,39.62) v1(52.83,18.41) v1(55.37,16.76) v1(58.72,35.1) v1(60.83,35.05) v1(61.72,9.02) v1(61.85,11.05) v1(63.07,35.08) v1(63.17,15.82) v1(64.01,8.26) v1(65.41,10.67) v1(65.51,15.88) v1(66.55,35) v1(67.64,8.05) v1(69.57,38.73) v1(69.6,37.41) v1(69.6,35.97) v1(70.1,8.26) v1(70.87,13.34) v1(71.5,6.22) v1(74.55,13.34) v1(74.8,6.22) v1(76.96,37.97) v1(79.63,38.86) v1(81.03,13.72) v1(81.15,22.35) v1(81.15,19.3) v1(81.15,15.49) v1(81.53,32.77) v1(81.79,37.08) v1(81.79,35.43) v1(81.92,26.04) v1(83.57,37.24) v1(83.57,35.48) v1(83.59,33.35) v1(83.57,17.91) v1(83.69,14.61) v1(83.82,22.1) v1(84.33,25.91) v2(3.3,11.68) v2(3.3,10.41) v2(4.57,11.68) v2(4.57,10.41) v2(21.08,15.62) v2(21.34,13.59) v2(22.61,15.24) v2(22.61,13.97) v2(24.13,31.11) v2(25.08,32.07) v2(25.08,31.11) v2(25.08,30.16) v2(26.04,31.11)
